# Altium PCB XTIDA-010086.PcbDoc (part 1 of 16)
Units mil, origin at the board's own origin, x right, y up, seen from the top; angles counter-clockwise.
Board outline 14763.78 x 8267.72 mil, 6 copper layers (Top Layer, GND Layer, Signal Layer 1, Signal Layer 2, Power Layer, Bottom Layer), stack 62 mil thick; 1933 components, 1002 nets, 4886 pads, 6482 vias.
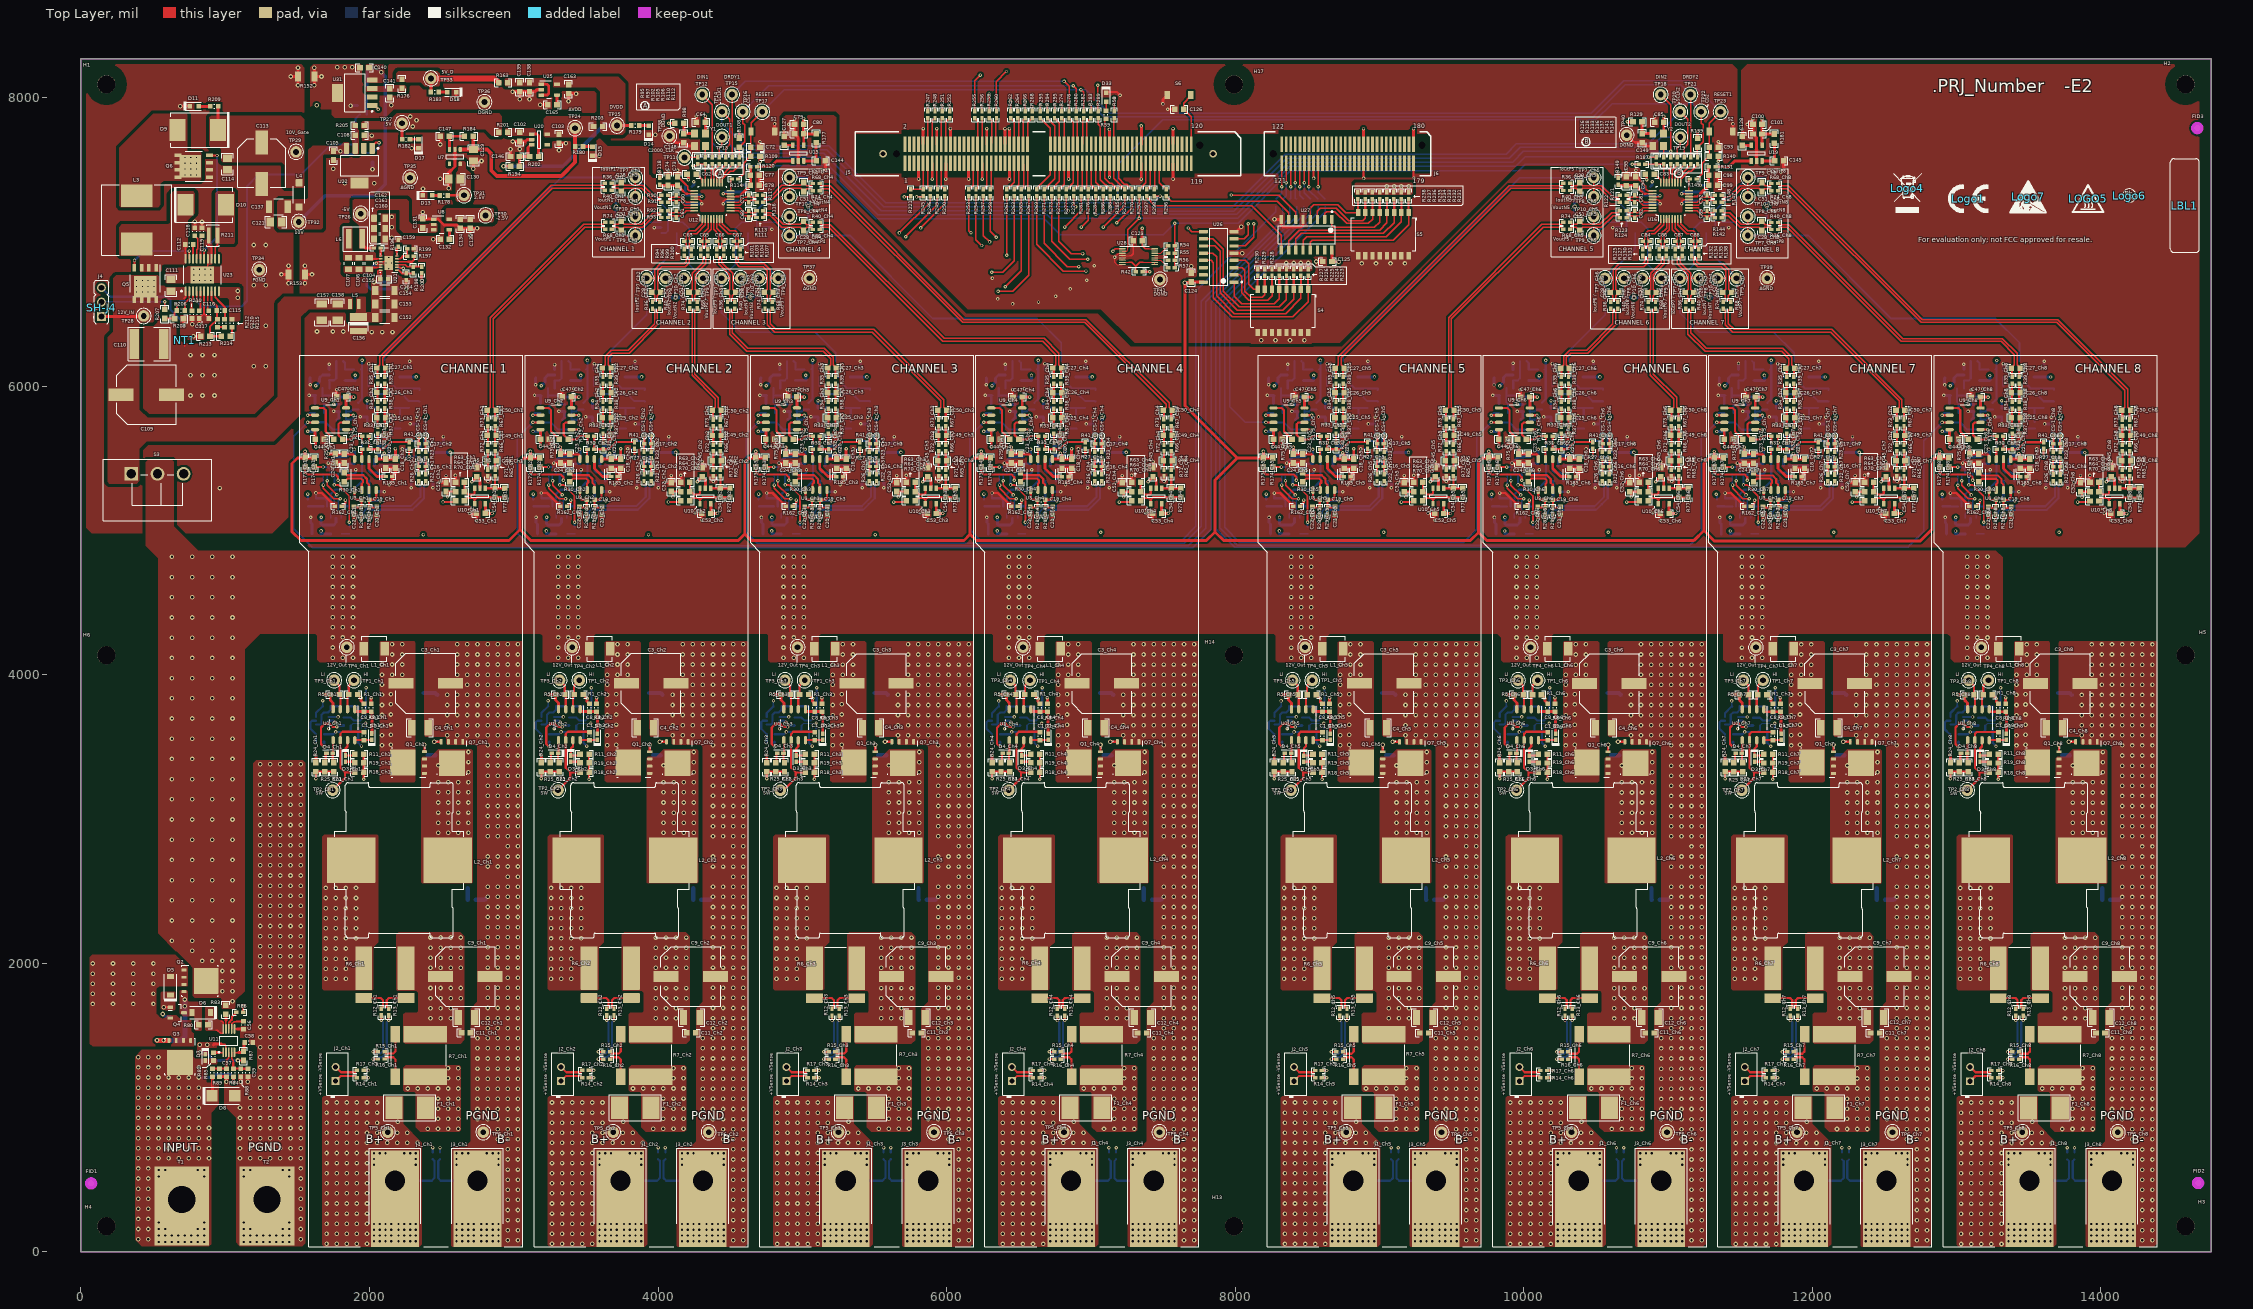
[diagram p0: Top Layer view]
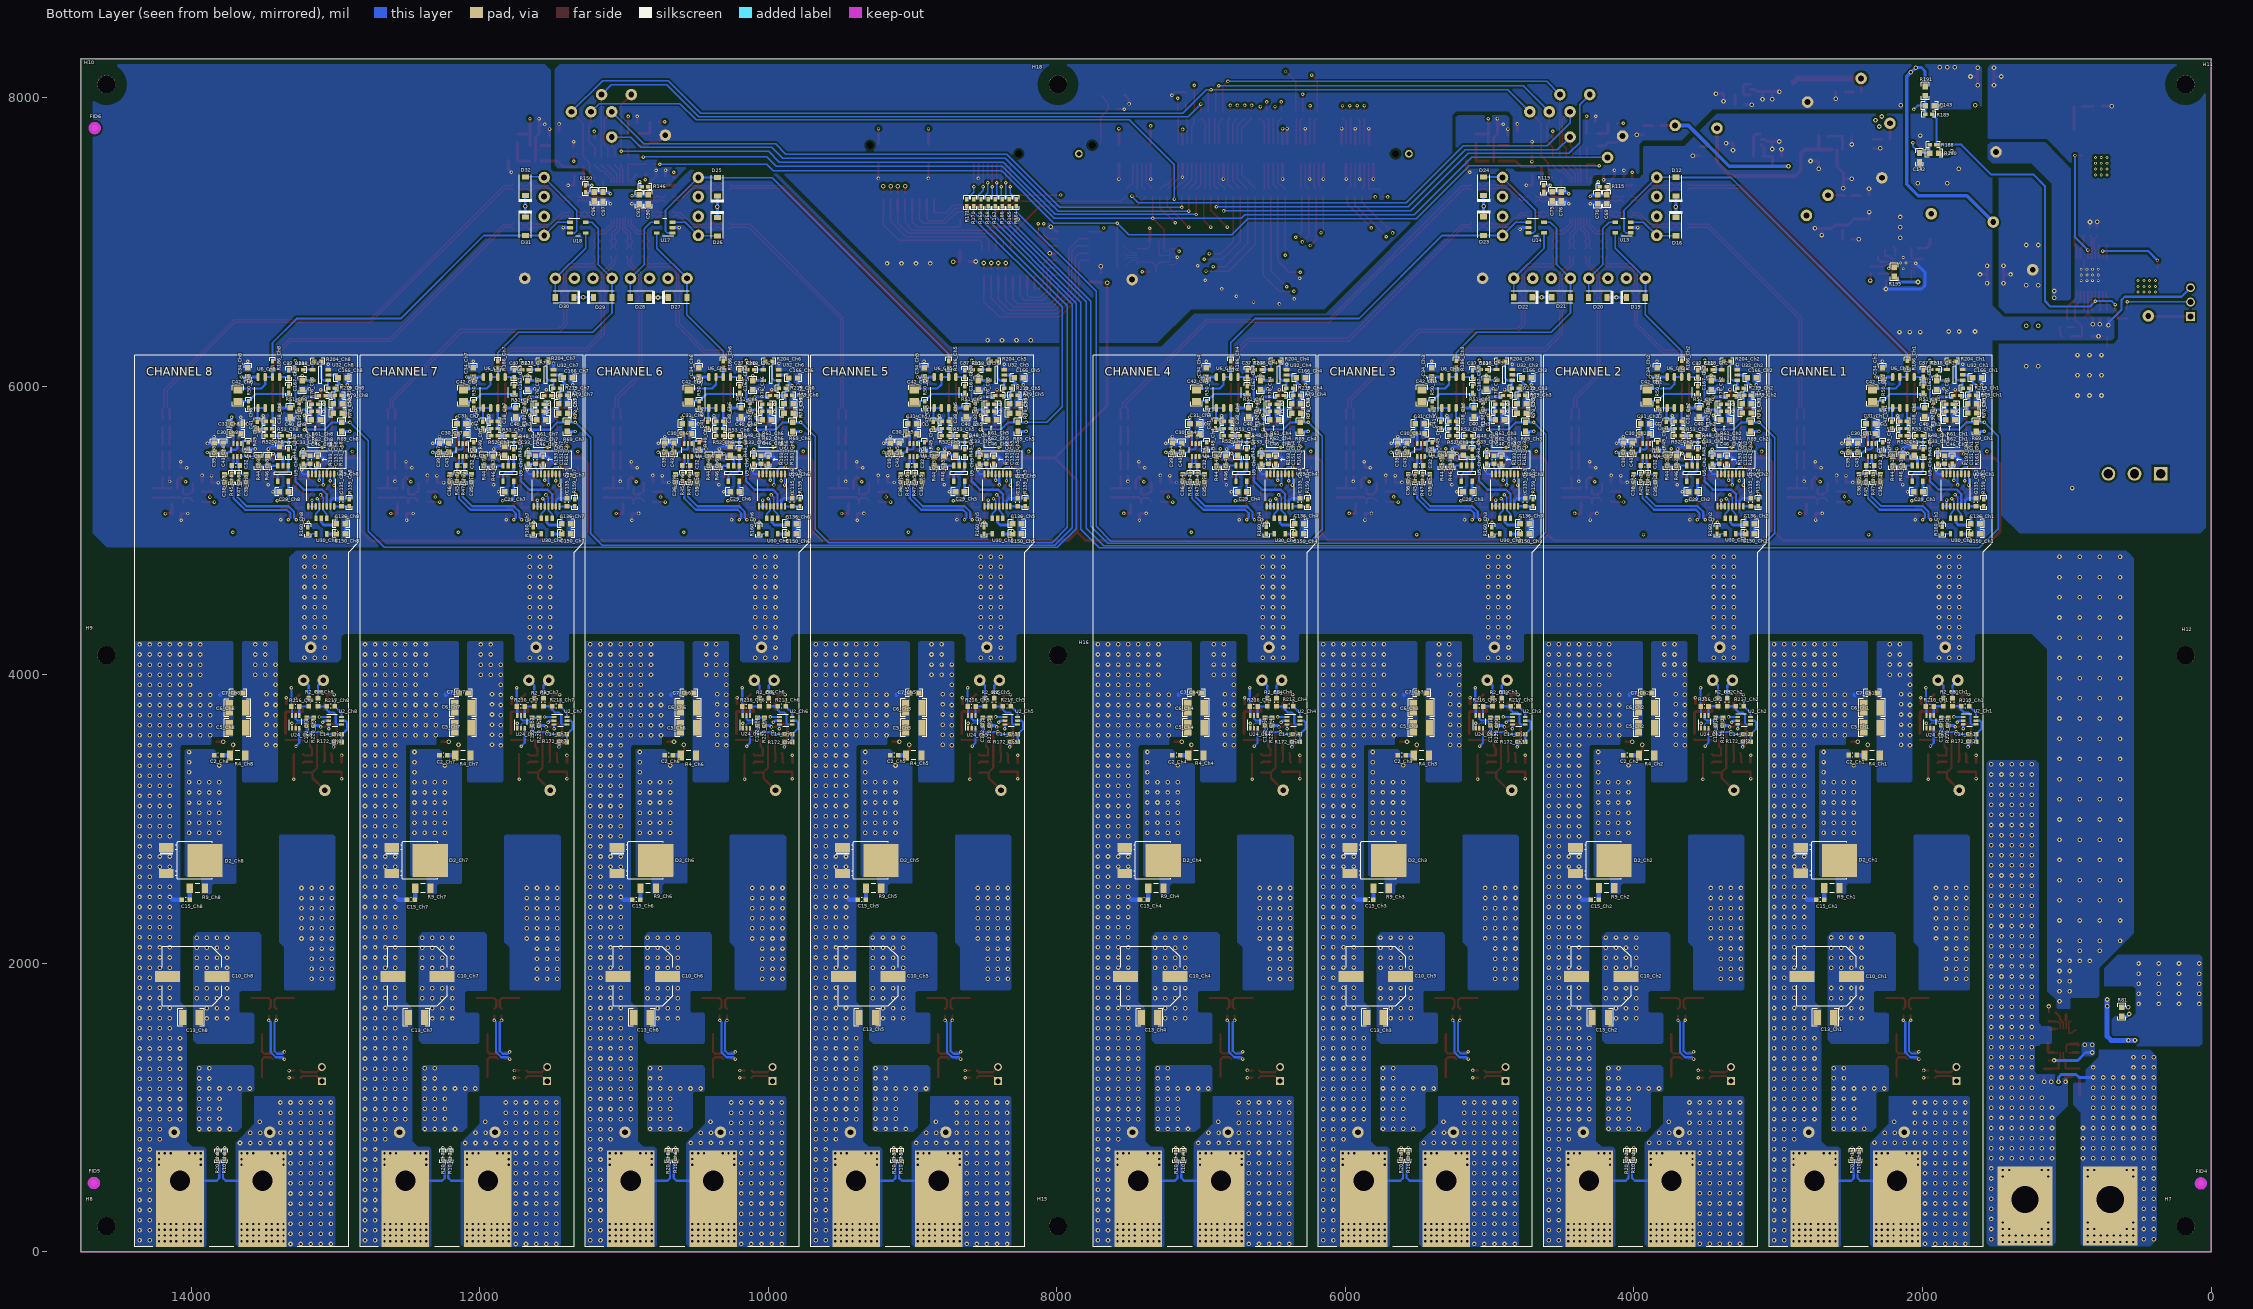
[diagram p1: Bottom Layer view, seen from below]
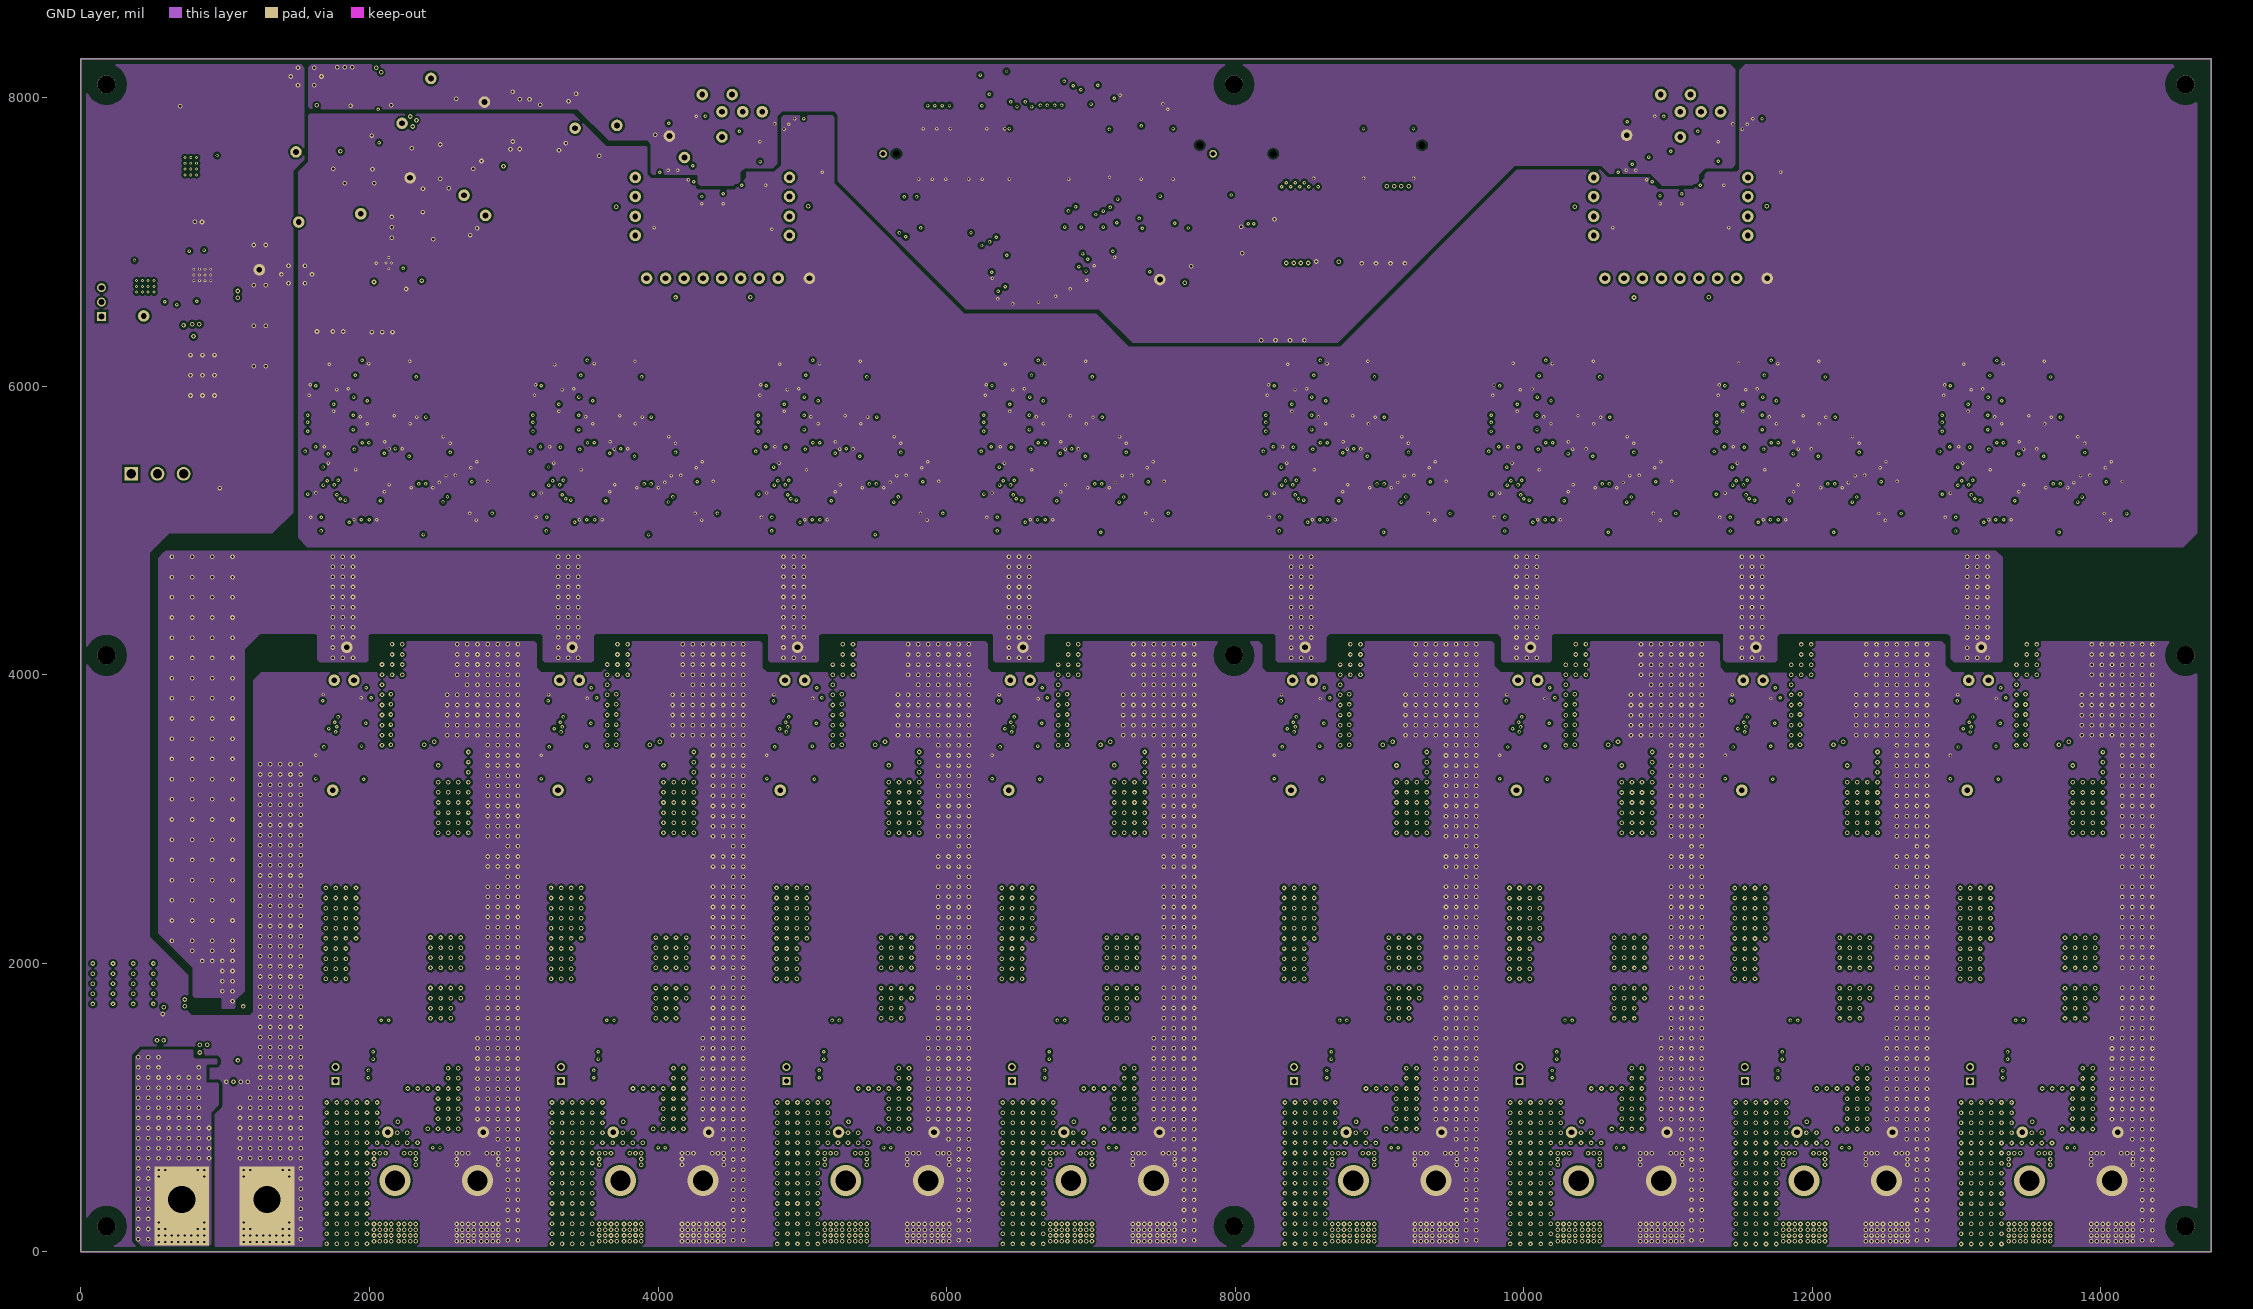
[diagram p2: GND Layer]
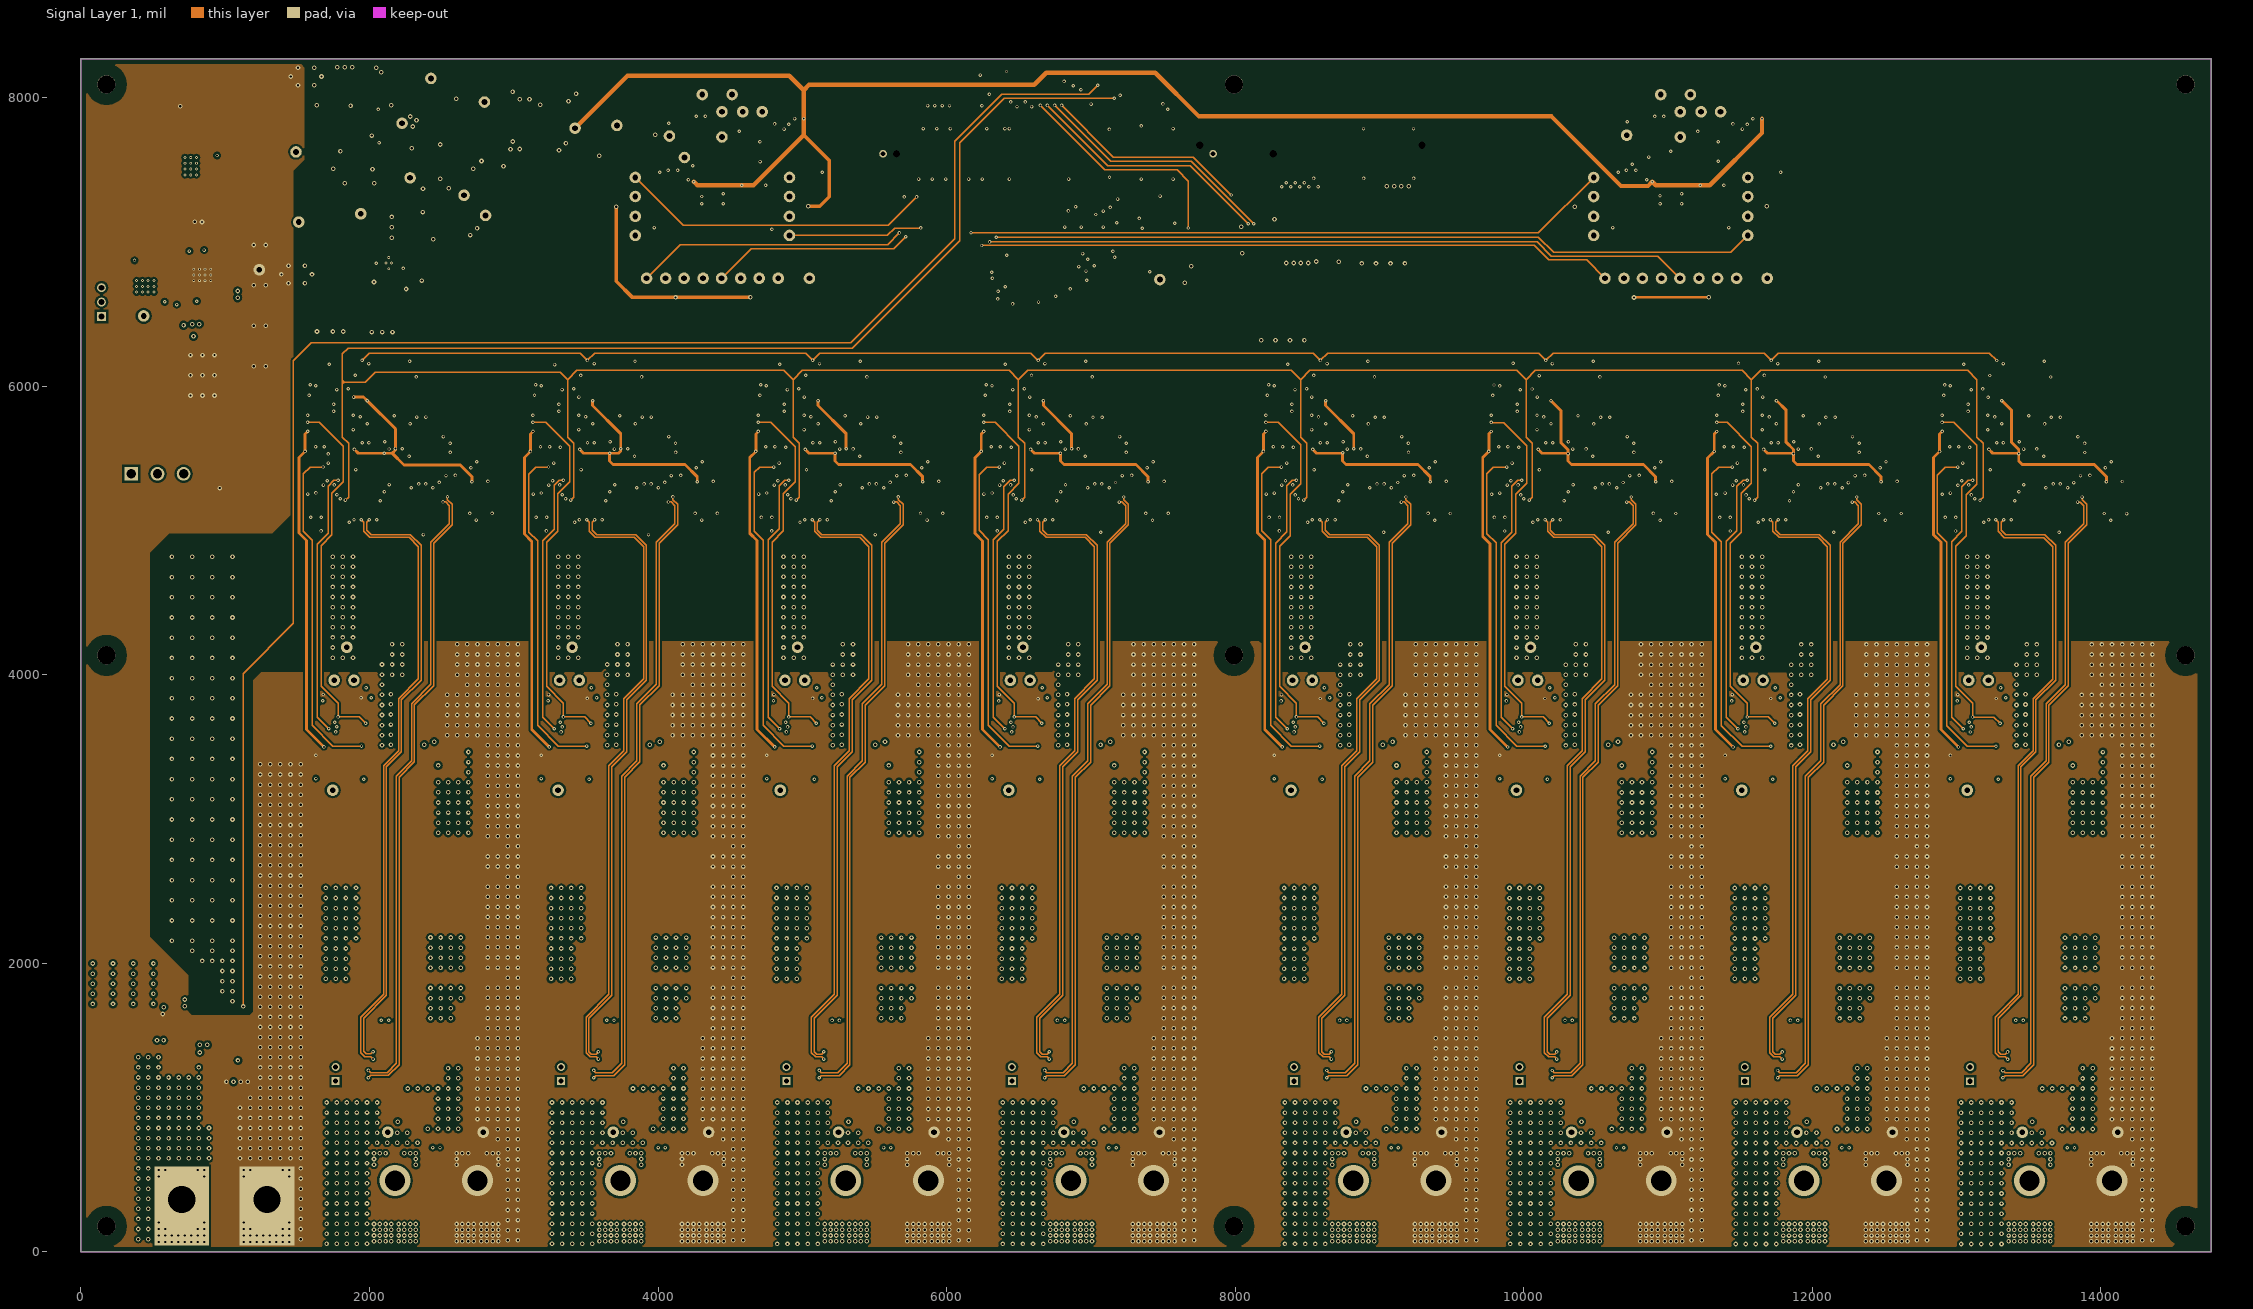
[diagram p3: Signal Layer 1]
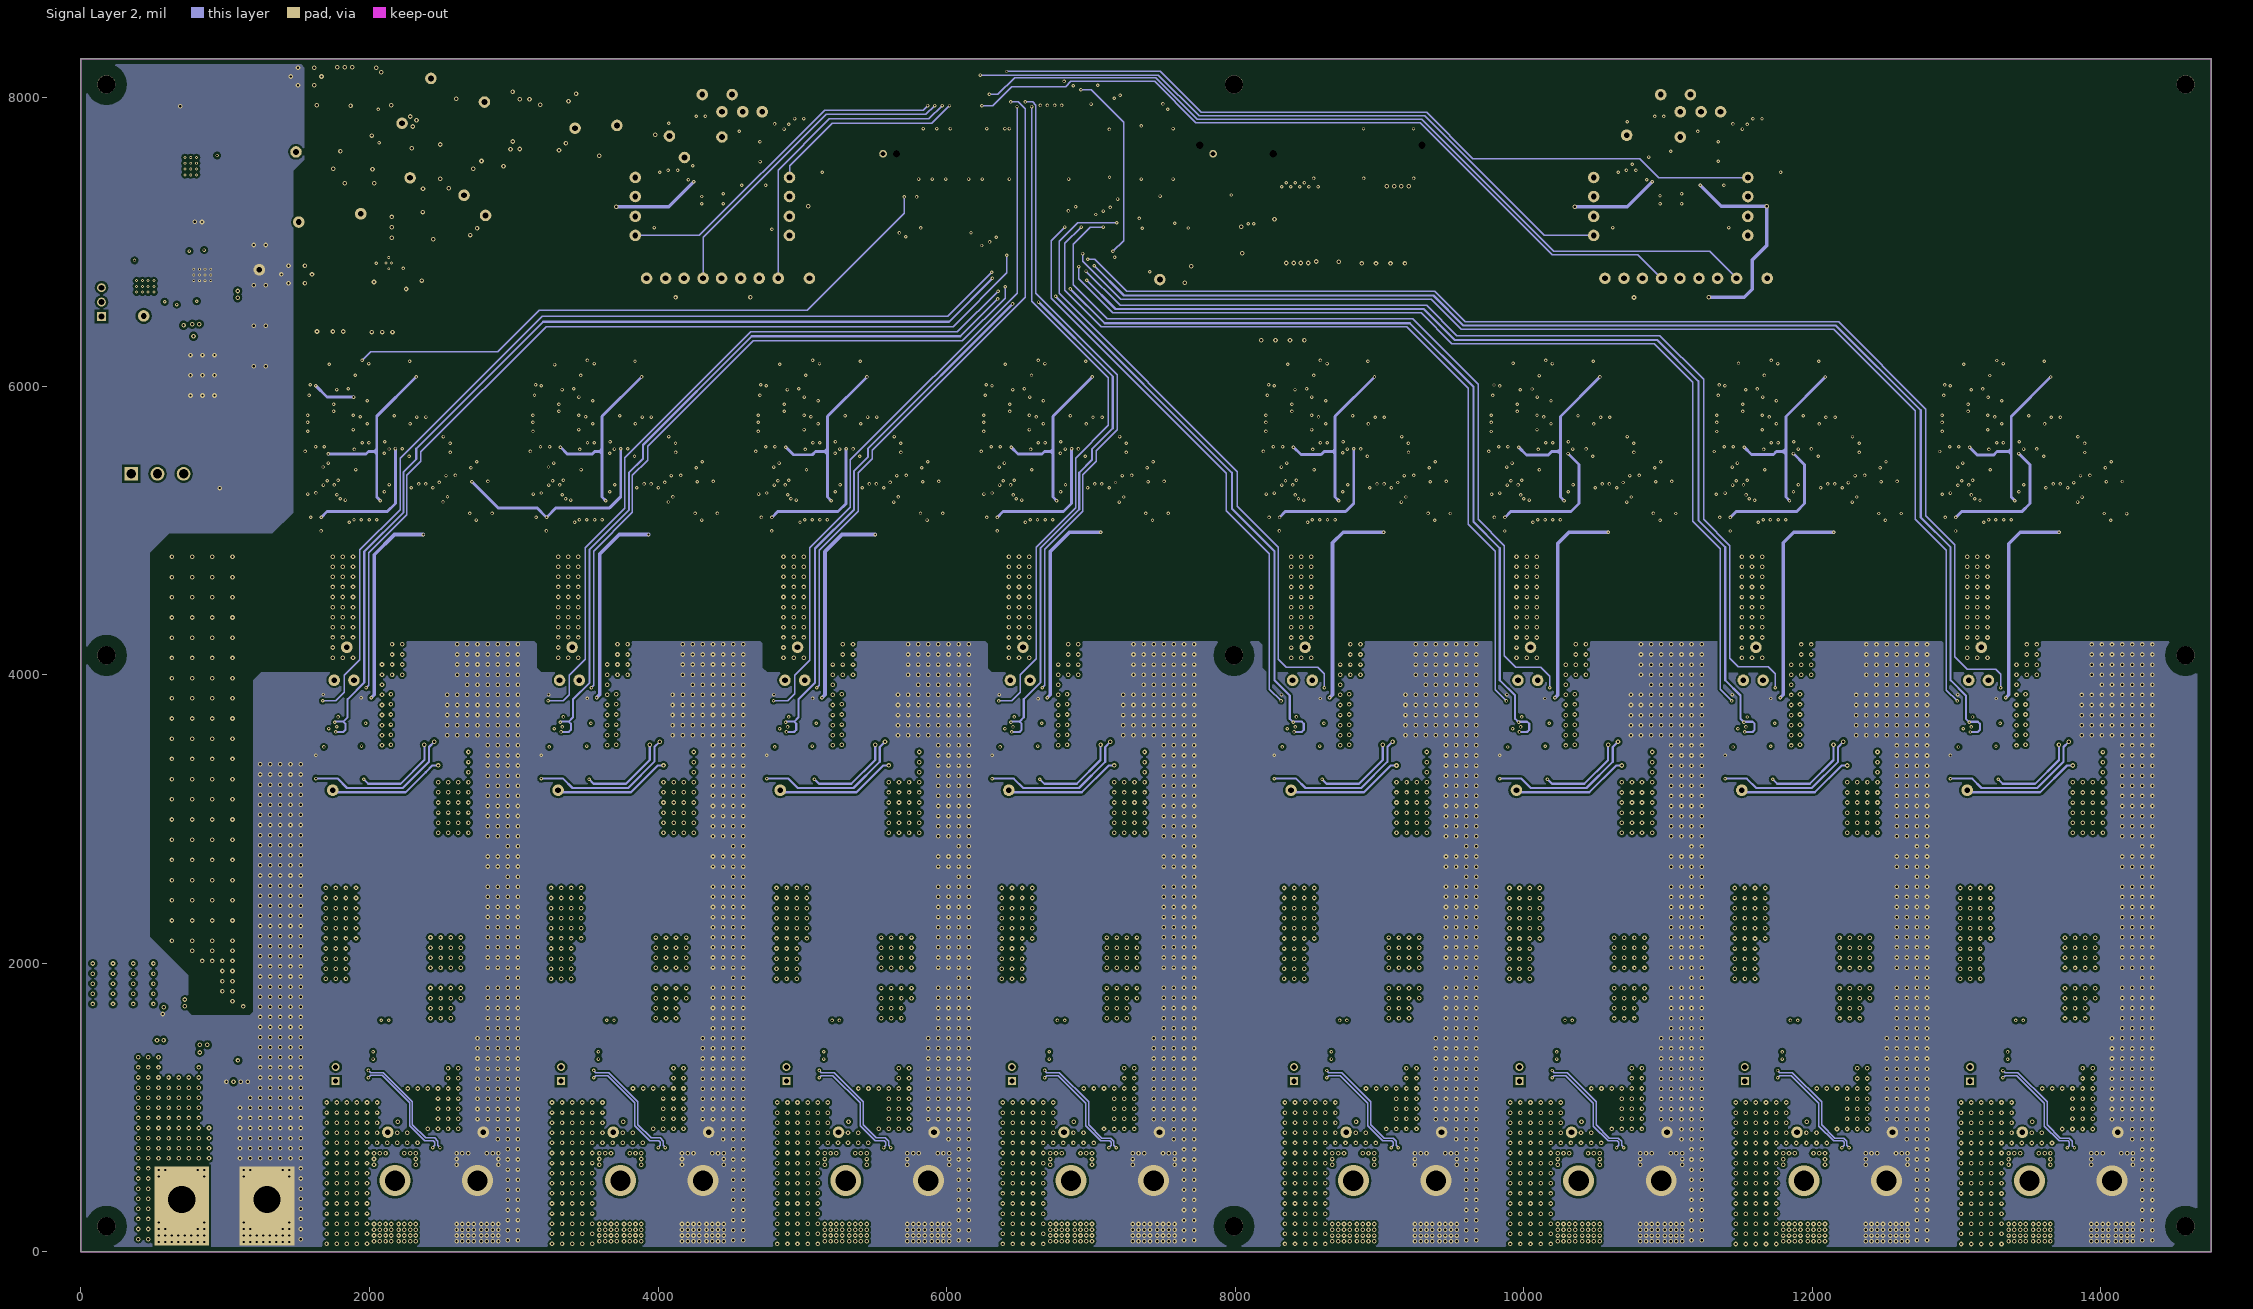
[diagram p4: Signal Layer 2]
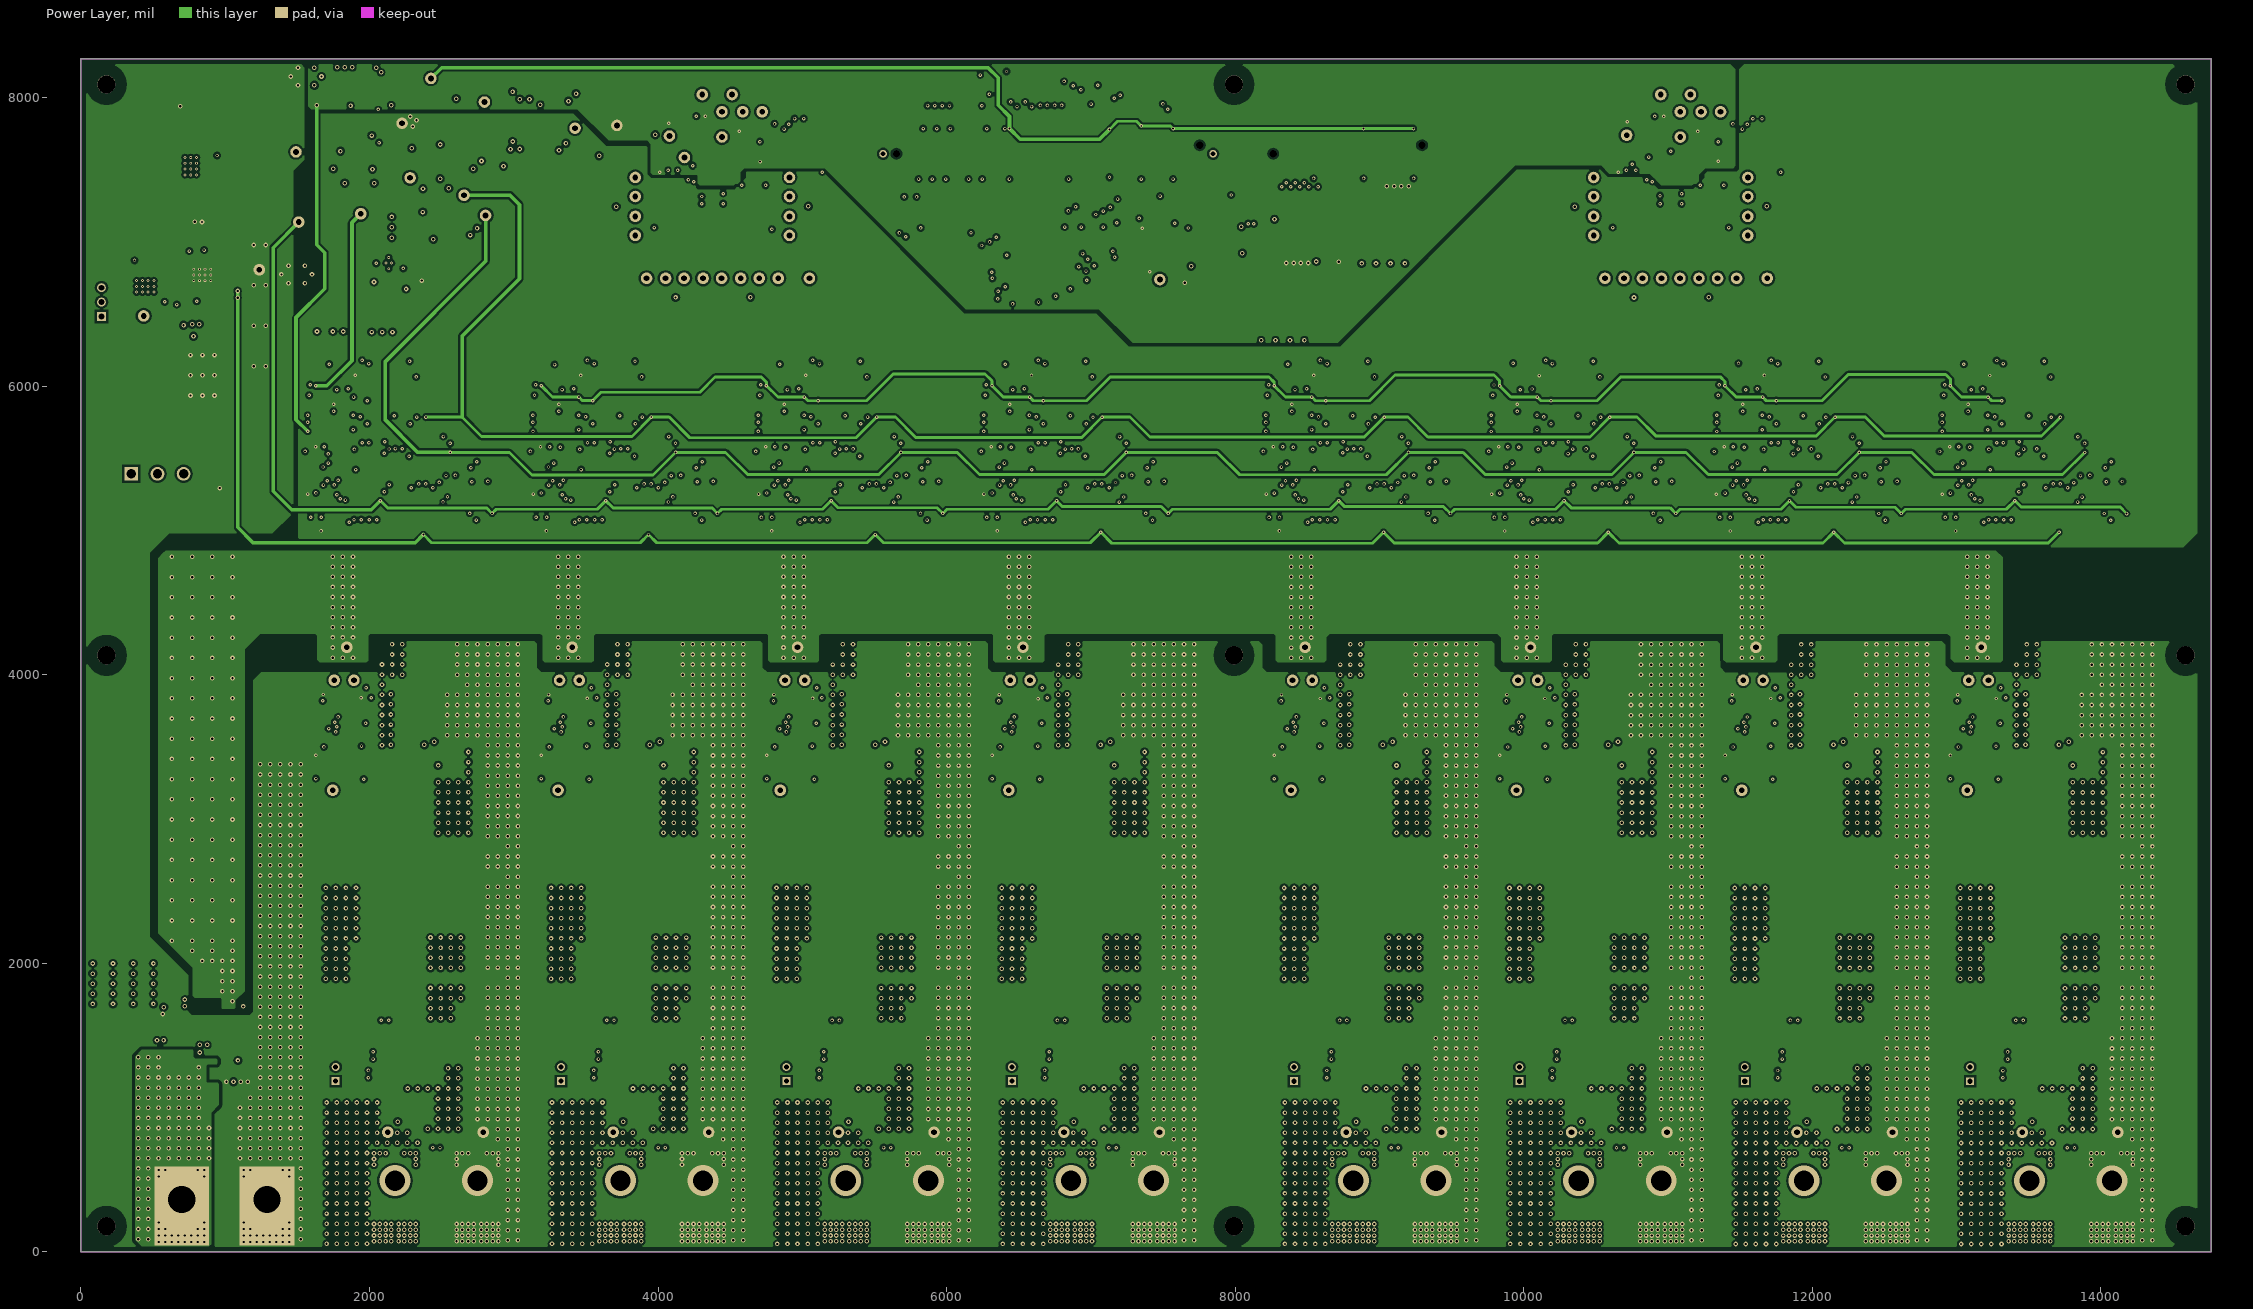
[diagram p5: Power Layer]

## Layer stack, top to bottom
Top Solder: solder mask 0.4, Solder Resist, Dk 3.5
Top Layer: signal copper 2.8
Dielectric 1: dielectric 8, FR-4 High Tg, Dk 4.2
GND Layer: signal copper 2.8
Dielectric2: core 8, FR-4 High Tg, Dk 4.8
Signal Layer 1: signal copper 1.4
Dielectric 3: dielectric 16, FR-4 High Tg, Dk 4.2
Signal Layer 2: signal copper 1.4
Dielectric 4: dielectric 8, FR-4 High Tg, Dk 4.2
Power Layer: signal copper 2.8
Dielectric 5: dielectric 8, FR-4 High Tg, Dk 4.2
Bottom Layer: signal copper 2.8
Bottom Solder: solder mask 0.4, Solder Resist, Dk 3.5

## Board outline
0,0 14763.78,0 14763.78,8267.72 0,8267.72

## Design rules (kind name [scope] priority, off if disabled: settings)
AcuteAngle [All] p1: minimum=4.50000000000000E+0001 checktracksonly=FALSE
AssemblyTestPointUsage [All] p1: valid=2
BoardOutlineClearance [All] p1: gap=25 ignorepadtopadclearanceinfootprint=FALSE
Clearance mounting_hole_clearence [InPadClass('mounting hole') vs InPolygon] p1: gap=80 ignorepadtopadclearanceinfootprint=FALSE
Clearance Clearance_Poly [InPolygon vs InPolygon] p2: gap=25 ignorepadtopadclearanceinfootprint=FALSE
Clearance "Clearance_poly to all" [inpoly] p3: gap=15 ignorepadtopadclearanceinfootprint=FALSE
Clearance [All] p4: gap=6 ignorepadtopadclearanceinfootprint=FALSE except(0: Arc-Arc Arc-SMDPad)
ComponentClearance ComponentClearance_MountingHoles_FiducialMarks [InComponentClass('Mounting Holes') vs InComponentClass('FiducialMark')] p1: gap=10 collisioncheckmode=3 verticalgap=10 showdistances=FALSE
ComponentClearance ComponentClearance_Shunt [InComponentClass('Header') vs InComponentClass('Shunt')] p2: gap=0 collisioncheckmode=3 verticalgap=0 showdistances=FALSE
ComponentClearance ComponentClearance_Logo [InComponentClass('Logo')] p3: gap=10 collisioncheckmode=3 verticalgap=10 showdistances=FALSE
ComponentClearance ComponentClearance_ScrewToNut [(HasFootprint('NY PMS 440 0025 PH')) vs (HasFootprint('Keystone_1902C'))] p4: gap=5 collisioncheckmode=3 verticalgap=10 showdistances=FALSE
ComponentClearance ComponentClearance_MountingHoles [InComponentClass('Mounting Holes')] p5: gap=1 collisioncheckmode=3 verticalgap=100000 showdistances=FALSE
ComponentClearance ComponentClearance_SmallPassives [HasFootprint('0201*') or HasFootprint('0402*') or HasFootprint('0508') or HasFootprint('0603*') or HasFootprint('0612') or HasFootprint('0805*') or HasFootprint('0815*') or HasFootprint('0830*') or HasFootprint('1206*') or HasFootprint('1210*') or HasFootprint('1808*') or HasFootprint('1812*') or HasFootprint('1825*') or HasFootprint('2010*') or HasFootprint('2220*') or HasFootprint('2225*') or HasFootprint('2512*') or HasFootprint('2728*') or HasFootprint('3518*') vs HasFootprint('0201*') or HasFootprint('0402*') or HasFootprint('0508') or HasFootprint('0603*') or HasFootprint('0612') or HasFootprint('0805*') or HasFootprint('0815*') or HasFootprint('0830*') or HasFootprint('1206*') or HasFootprint('1210*') or HasFootprint('1808*') or HasFootprint('1812*') or HasFootprint('1825*') or HasFootprint('2010*') or HasFootprint('2220*') or HasFootprint('2225*') or HasFootprint('2512*') or HasFootprint('2728*') or HasFootprint('3518*')] p6: gap=3 collisioncheckmode=3 verticalgap=3 showdistances=FALSE
ComponentClearance ComponentClearance_THtoSMT [IsThruComponent vs IsSMTComponent] p7: gap=0 collisioncheckmode=3 verticalgap=0 showdistances=FALSE
ComponentClearance ComponentClearance_THtoTH [IsThruComponent vs IsThruComponent] p8: gap=10 collisioncheckmode=3 verticalgap=10 showdistances=FALSE
ComponentClearance [All] p9: gap=1 collisioncheckmode=3 verticalgap=1 showdistances=FALSE
DiffPairsRouting [All] p1: maxlimit=100 minlimit=10 mostfreqgap=10 toplayer_minwidth=10 toplayer_maxwidth=15 toplayer_prefwidth=10 midlayer1_minwidth=10 midlayer1_maxwidth=15 midlayer1_prefwidth=10 midlayer2_minwidth=10 midlayer2_maxwidth=15 midlayer2_prefwidth=10 midlayer3_minwidth=10 midlayer3_maxwidth=15 midlayer3_prefwidth=10 midlayer4_minwidth=10 midlayer4_maxwidth=15 midlayer4_prefwidth=10 bottomlayer_minwidth=10 bottomlayer_maxwidth=15 bottomlayer_prefwidth=10 maxuncoupledlength=1000
FabricationTestPointUsage TestPointUsage [All] p1: valid=2 allowmultiple=FALSE
FabricationTestpoint Testpoint [All] p1: side=3 testpointundercomponent=TRUE minsize=40 maxsize=100 preferedsize=60 minholesize=0 maxholesize=40 preferedholesize=32 testpointgrid=1 allowsidetop=TRUE allowsidebottom=TRUE usegrid=TRUE gridtolerance=0.01
FanoutControl Fanout_LCC [IsLCC] p1: bgadir=Out bgaviamode=Centered fanoutstyle=Auto fanoutdirection=Alternating viagrid=1 // Fanout_LCC (Default Rule)
FanoutControl Fanout_BGA [IsBGA] p2: bgadir=Out bgaviamode=Centered fanoutstyle=Auto fanoutdirection=Alternating viagrid=1 // Fanout_BGA (Default Rule)
FanoutControl Fanout_Default [All] p4: bgadir=Out bgaviamode=Centered fanoutstyle=Auto fanoutdirection=Alternating viagrid=1 // Fanout_Default (Default Rule)
FanoutControl Fanout_Small [(CompPinCount < 5)] p5: bgadir=Out bgaviamode=Centered fanoutstyle=Auto fanoutdirection=OutThenIn viagrid=1 // Fanout_Small (Default Rule)
HoleSize [All] p1: absolutevalues=TRUE maxlimit=251 minlimit=7.87 maxpercent=80.000 minpercent=20.000
MinimumAnnularRing MinimumAnnularRing_ThermalPadVias [IsVia and InAnyComponent] p1: minimumring=5.91
MinimumAnnularRing [All] p2: minimumring=6
MinimumSolderMaskSliver MinimumSolderMaskSliver_Logo [InComponentClass('Logo') vs InComponentClass('Logo')] p1: minsoldermaskwidth=0.7
MinimumSolderMaskSliver [All] p2: minsoldermaskwidth=3.94
PlaneConnect [All] p1: planeconnectstyle=Direct reliefexpansion=10 reliefentries=4 reliefconductorwidth=10 reliefairgap=10
PolygonConnect [All] p1: connectstyle=Direct reliefconductorwidth=10 reliefentries=4 polygonreliefangle="90 Angle" airgapwidth=10
RoomDefinition Hardware [InComponentClass('Hardware')] p1: confinementstyle=ConfineIn formatcopy=TRUE lockcomponents=FALSE outline -1666.26,-1884.85 333.74,-1884.85 333.74,-884.85 -1666.26,-884.85
RoomDefinition "Control Card_28379" [InComponentClass('Control Card_28379')] p2: confinementstyle=ConfineIn formatcopy=TRUE lockcomponents=FALSE outline 5211.39,6377 11079,6377 11079,7785 5211.39,7785
RoomDefinition "Bias Power Supply" [InComponentClass('Bias Power Supply')] p3: confinementstyle=ConfineIn formatcopy=TRUE lockcomponents=FALSE outline 2934.53,5606.32 2934.53,7974.32 73.53,7974.32 73.53,5606.32
RoomDefinition "MAIN SHEET" [InComponentClass('MAIN SHEET')] p4: confinementstyle=ConfineIn formatcopy=TRUE lockcomponents=FALSE outline 1520,-707.44 1520,2159.56 281,2159.56 281,-707.44
RoomDefinition Ch8 [InComponentClass('Ch8')] p5: confinementstyle=ConfineIn formatcopy=TRUE lockcomponents=FALSE outline 14390.7,-432.55 12857.7,-432.55 12857.7,6168 14390.7,6168
RoomDefinition Ch7 [InComponentClass('Ch7')] p6: confinementstyle=ConfineIn formatcopy=TRUE lockcomponents=FALSE outline 12828.7,-432.47 11295.7,-432.47 11295.7,6175 12828.7,6175
RoomDefinition Ch6 [InComponentClass('Ch6')] p7: confinementstyle=ConfineIn formatcopy=TRUE lockcomponents=FALSE outline 11266.7,-432.39 9733.7,-432.39 9733.7,6174 11266.7,6174
RoomDefinition Ch5 [InComponentClass('Ch5')] p8: confinementstyle=ConfineIn formatcopy=TRUE lockcomponents=FALSE outline 9704.7,-432.31 8171.7,-432.31 8171.7,6173 9704.7,6173
RoomDefinition Ch4 [InComponentClass('Ch4')] p9: confinementstyle=ConfineIn formatcopy=TRUE lockcomponents=FALSE outline 7749,-432.24 6216,-432.24 6216,6172 7749,6172
RoomDefinition Ch3 [InComponentClass('Ch3')] p10: confinementstyle=ConfineIn formatcopy=TRUE lockcomponents=FALSE outline 6187,-432.16 4654,-432.16 4654,6170 6187,6170
RoomDefinition Ch2 [InComponentClass('Ch2')] p11: confinementstyle=ConfineIn formatcopy=TRUE lockcomponents=FALSE outline 4625,-432.08 3092,-432.08 3092,6174 4625,6174
RoomDefinition Ch1 [InComponentClass('Ch1')] p12: confinementstyle=ConfineIn formatcopy=TRUE lockcomponents=FALSE outline 3087,-432 1554,-432 1554,6173 3087,6173
RoomDefinition ADC [InComponentClass('ADC')] p13: confinementstyle=ConfineIn formatcopy=TRUE lockcomponents=FALSE outline 2996.42,6382.73 13743.42,6382.73 13743.42,8068.73 2996.42,8068.73
RoutingVias ThermalPadVias [IsVia and InAnyComponent] p1: holewidth=7.87 width=19.68 viastyle="Through Hole" minholewidth=7.87 minwidth=19.68 maxholewidth=12.99 maxwidth=23.62
RoutingVias [All] p2: holewidth=16 width=32 viastyle="Through Hole" minholewidth=12 minwidth=24 maxholewidth=16 maxwidth=32
SilkToBoardRegionClearance [Not ((IsComment or IsDesignator) And (Hide <> 'False')) and not InRegion(1000,500,4000,800)] p1:
SilkToSilkClearance SilkToSilkClearance_Pb-FreeLogo [(HasFootprint('Pb-Free_Overlay_Medium') OR HasFootprint('Pb-Free_Overlay_Small')) vs (HasFootprint('Pb-Free_Overlay_Medium') OR HasFootprint('Pb-Free_Overlay_Small'))] p1: silktosilkclearance=0
SilkToSilkClearance [All] p2: silktosilkclearance=2
SilkToSolderMaskClearance SilkToComponentPadClearance [(IsPad or IsFill or IsRegion) and InAnycomponent] p1: minsilkscreentomaskgap=5 clearancetoexposedcopper=TRUE
SilkToSolderMaskClearance "Silk to Solder Mask Opening" [All] p2: minsilkscreentomaskgap=4 clearancetoexposedcopper=FALSE
SolderMaskExpansion [All] p1: expansion=1.97
Width [All] p1: maxlimit=100 minlimit=6 preferedwidth=10 checkconnectedcopper=TRUE
15 further rules are at their usual default settings.

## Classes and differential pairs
net class Interrupt[1..8]: Interrupt1 Interrupt2 Interrupt3 Interrupt4 Interrupt5 Interrupt6 Interrupt7 Interrupt8
channel class "XTIDA-010086_Power Stage": Ch1 Ch2 Ch3 Ch4 Ch5 Ch6 Ch7 Ch8
component class "Control Card_28379": C124 C125 C126 D33 J5 J6 R58 R59 R164 R165 R166 R167 R168 R169 R170 R171 R221 R223 R224 R225 R226 R227 R228 R229 R230 R231 R232 R233 R234 R235 R236 R237 R238 R245 R246 R247 R248 R249 R250 R251 R252 R253 R254 R255 R256 R257 R258 R259 R260 R261 R262 R263 R264 R265 R266 R267 R268 R269 R270 R271 R272 R273 R274 R275 R276 R277 R278 R279 R280 R281 R282 R283 R284 R285 R286 R288 R289 R292 R293 R294 R295 R296 R297 R298 S4 S5 S6 TP41 U26 U27
differential pair class 100Ohm: ADC_Iout1 ADC_Iout2 ADC_Iout3 ADC_Iout4 ADC_Iout5 ADC_Iout6 ADC_Iout7 ADC_Iout8 ADC_Vout1 ADC_Vout2 ADC_Vout3 ADC_Vout4 ADC_Vout5 ADC_Vout6 ADC_Vout7 ADC_Vout8 Ch1_Iout1 Ch1_Vout1 Ch2_Iout2 Ch2_Vout2 Ch3_Iout3 Ch3_Vout3 Ch4_Iout4 Ch4_Vout4 Ch5_Iout5 Ch5_Vout5 Ch6_Iout6 Ch6_Vout6 Ch7_Iout7 Ch7_Vout7 Ch8_Iout8 Ch8_Vout8 CS_CH1 CS_CH2 CS_CH3 CS_CH4 CS_CH5 CS_CH6 CS_CH7 CS_CH8 Iout1 Iout2 Iout3 Iout4 Iout5 Iout6 Iout7 Iout8 R_CS_CH1 Vout1 Vout2 Vout3 Vout4 Vout5 Vout6 Vout7 Vout8 VSense_CH1 VSense_CH2 VSense_CH3 VSense_CH4 VSense_CH5 VSense_CH6 VSense_CH7 VSense_CH8
component class ADC: C60 C61 C62 C63 C64 C65 C66 C67 C68 C69 C70 C71 C72 C73 C74 C75 C76 C77 C78 C79 C80 C81 C82 C83 C84 C85 C86 C87 C88 C89 C90 C91 C92 C93 C94 C95 C96 C97 C98 C99 C100 C101 C123 C127 C128 C144 C145 C148 C149 D12 D16 D19 D20 D21 D22 D23 D24 D25 D26 D27 D28 D29 D30 D31 D32 R42 R54 R55 R56 R57 R90 R91 R92 R93 R94 R95 R96 R97 R98 R99 R100 R101 R102 R103 R104 R105 R106 R107 R108 R109 R110 R111 R112 R113 R114 R115 R116 R117 R118 R119 R120 R121 R122 R123 R124 R125 R126 R127 R128 R129 R130 R131 R132 R133 R134 R135 R136 R137 R138 R139 R140 R141 R142 R143 R144 R145 R146 R147 R148 R149 R150 R151 R152 R153 R177 R181 R187 S1 S2 TP11 TP12 TP13 TP14 TP15 TP16 TP17 TP18 TP19 TP20 TP21 TP22 TP23 TP37 TP38 TP39 TP40 U12 U13 U14 U15 U16 U17 U18 U19 U28 Y1 Y2
net class VoutP[1..8]: VoutP1 VoutP2 VoutP3 VoutP4 VoutP5 VoutP6 VoutP7 VoutP8
net class VoutN[1..8]: VoutN1 VoutN2 VoutN3 VoutN4 VoutN5 VoutN6 VoutN7 VoutN8
net class IoutP[1..8]: IoutP1 IoutP2 IoutP3 IoutP4 IoutP5 IoutP6 IoutP7 IoutP8
net class IoutN[1..8]: IoutN1 IoutN2 IoutN3 IoutN4 IoutN5 IoutN6 IoutN7 IoutN8
net class EPWM_B[1..8]: EPWM_B1 EPWM_B2 EPWM_B3 EPWM_B4 EPWM_B5 EPWM_B6 EPWM_B7 EPWM_B8
net class EPWM_A[1..8]: EPWM_A1 EPWM_A2 EPWM_A3 EPWM_A4 EPWM_A5 EPWM_A6 EPWM_A7 EPWM_A8
component class "MAIN SHEET": C56 C57 C58 C59 D5 D6 D7 D8 Q2 Q3 Q4 R80 R81 R82 R83 R84 R85 R86 R87 R88 R89 T1 T2 U11
component class Ch8: C1_Ch8 C2_Ch8 C3_Ch8 C4_Ch8 C5_Ch8 C6_Ch8 C7_Ch8 C8_Ch8 C9_Ch8 C10_Ch8 C11_Ch8 C12_Ch8 C13_Ch8 C14_Ch8 C15_Ch8 C16_Ch8 C17_Ch8 C18_Ch8 C19_Ch8 C20_Ch8 C21_Ch8 C22_Ch8 C23_Ch8 C24_Ch8 C25_Ch8 C26_Ch8 C27_Ch8 C28_Ch8 C29_Ch8 C30_Ch8 C31_Ch8 C32_Ch8 C33_Ch8 C34_Ch8 C35_Ch8 C36_Ch8 C37_Ch8 C38_Ch8 C39_Ch8 C40_Ch8 C41_Ch8 C42_Ch8 C43_Ch8 C44_Ch8 C45_Ch8 C46_Ch8 C47_Ch8 C48_Ch8 C49_Ch8 C50_Ch8 C51_Ch8 C52_Ch8 C53_Ch8 C54_Ch8 C55_Ch8 C56_Ch8 C57_Ch8 C58_Ch8 C59_Ch8 C60_Ch8 C61_Ch8 C62_Ch8 C63_Ch8 C64_Ch8 C65_Ch8 C66_Ch8 C67_Ch8 C68_Ch8 C69_Ch8 C70_Ch8 C71_Ch8 C72_Ch8 C73_Ch8 C74_Ch8 C75_Ch8 C76_Ch8 C77_Ch8 C78_Ch8 C79_Ch8 C80_Ch8 C81_Ch8 C82_Ch8 C83_Ch8 C84_Ch8 C85_Ch8 C86_Ch8 C87_Ch8 C88_Ch8 C89_Ch8 C90_Ch8 C91_Ch8 C92_Ch8 C93_Ch8 C94_Ch8 C95_Ch8 C96_Ch8 C97_Ch8 C98_Ch8 C99_Ch8 C100_Ch8 C101_Ch8 C102_Ch8 C103_Ch8 C122_Ch8 C135_Ch8 C136_Ch8 C150_Ch8 C151_Ch8 C166_Ch8 C167_Ch8 CS+1_Ch8 CS-1_Ch8 D1_Ch8 D2_Ch8 D3_Ch8 D4_Ch8 D5_Ch8 D6_Ch8 D7_Ch8 D10_Ch8 F1_Ch8 J1_Ch8 J2_Ch8 J3_Ch8 L1_Ch8 L2_Ch8 Q1_Ch8 Q7_Ch8 R1_Ch8 R2_Ch8 R3_Ch8 R4_Ch8 R5_Ch8 R6_Ch8 R7_Ch8 R8_Ch8 R9_Ch8 R10_Ch8 R11_Ch8 R12_Ch8 R13_Ch8 R14_Ch8 R15_Ch8 R16_Ch8 R17_Ch8 R18_Ch8 R19_Ch8 R20_Ch8 R21_Ch8 R22_Ch8 R23_Ch8 R24_Ch8 R25_Ch8 R26_Ch8 R27_Ch8 R28_Ch8 R29_Ch8 R30_Ch8 R31_Ch8 R32_Ch8 R33_Ch8 R34_Ch8 R35_Ch8 R36_Ch8 R37_Ch8 R38_Ch8 R39_Ch8 R40_Ch8 R41_Ch8 R43_Ch8 R44_Ch8 R45_Ch8 R46_Ch8 R47_Ch8 R48_Ch8 R49_Ch8 R50_Ch8 R51_Ch8 R52_Ch8 R53_Ch8 R61_Ch8 R62_Ch8 R63_Ch8 R64_Ch8 R65_Ch8 R66_Ch8 R67_Ch8 R68_Ch8 R69_Ch8 R70_Ch8 R71_Ch8 R72_Ch8 R73_Ch8 R74_Ch8 R75_Ch8 R76_Ch8 R77_Ch8 R78_Ch8 R79_Ch8 R93_Ch8 R95_Ch8 R96_Ch8 R97_Ch8 R98_Ch8 R99_Ch8 R100_Ch8 R101_Ch8 R102_Ch8 R103_Ch8 R104_Ch8 R105_Ch8 R107_Ch8 R110_Ch8 R111_Ch8 R113_Ch8 R114_Ch8 R115_Ch8 R116_Ch8 R117_Ch8 R118_Ch8 R119_Ch8 R120_Ch8 R121_Ch8 R122_Ch8 R123_Ch8 R124_Ch8 R125_Ch8 R126_Ch8 R127_Ch8 R128_Ch8 R129_Ch8 R130_Ch8 R131_Ch8 R132_Ch8 R133_Ch8 R134_Ch8 R138_Ch8 R139_Ch8 R140_Ch8 R141_Ch8 R142_Ch8 R143_Ch8 R144_Ch8 R145_Ch8 R146_Ch8 R147_Ch8 R148_Ch8 R149_Ch8 R150_Ch8 R151_Ch8 R152_Ch8 R153_Ch8 R154_Ch8 R155_Ch8 R158_Ch8 R159_Ch8 R160_Ch8 R161_Ch8 R162_Ch8 R164_Ch8 R165_Ch8 R166_Ch8 R167_Ch8 R168_Ch8 R169_Ch8 R170_Ch8 R171_Ch8 R172_Ch8 R173_Ch8 R174_Ch8 R175_Ch8 R176_Ch8 R185_Ch8 R186_Ch8 R192_Ch8 R193_Ch8 R204_Ch8 R216_Ch8 R217_Ch8 R218_Ch8 R219_Ch8 R220_Ch8 TP1_Ch8 TP2_Ch8 TP3_Ch8 TP4_Ch8 TP5_Ch8 TP6_Ch8 TP7_Ch8 TP8_Ch8 TP9_Ch8 TP10_Ch8 U1_Ch8 U2_Ch8 U3_Ch8 U4_Ch8 U5_Ch8 U6_Ch8 U9_Ch8 U10_Ch8 U17_Ch8 U18_Ch8 U19_Ch8 U20_Ch8 U21_Ch8 U22_Ch8 U24_Ch8 U29_Ch8 U30_Ch8 U32_Ch8
component class Ch7: C1_Ch7 C2_Ch7 C3_Ch7 C4_Ch7 C5_Ch7 C6_Ch7 C7_Ch7 C8_Ch7 C9_Ch7 C10_Ch7 C11_Ch7 C12_Ch7 C13_Ch7 C14_Ch7 C15_Ch7 C16_Ch7 C17_Ch7 C18_Ch7 C19_Ch7 C20_Ch7 C21_Ch7 C22_Ch7 C23_Ch7 C24_Ch7 C25_Ch7 C26_Ch7 C27_Ch7 C28_Ch7 C29_Ch7 C30_Ch7 C31_Ch7 C32_Ch7 C33_Ch7 C34_Ch7 C35_Ch7 C36_Ch7 C37_Ch7 C38_Ch7 C39_Ch7 C40_Ch7 C41_Ch7 C42_Ch7 C43_Ch7 C44_Ch7 C45_Ch7 C46_Ch7 C47_Ch7 C48_Ch7 C49_Ch7 C50_Ch7 C51_Ch7 C52_Ch7 C53_Ch7 C54_Ch7 C55_Ch7 C56_Ch7 C57_Ch7 C58_Ch7 C59_Ch7 C60_Ch7 C61_Ch7 C62_Ch7 C63_Ch7 C64_Ch7 C65_Ch7 C66_Ch7 C67_Ch7 C68_Ch7 C69_Ch7 C70_Ch7 C71_Ch7 C72_Ch7 C73_Ch7 C74_Ch7 C75_Ch7 C76_Ch7 C77_Ch7 C78_Ch7 C79_Ch7 C80_Ch7 C81_Ch7 C82_Ch7 C83_Ch7 C84_Ch7 C85_Ch7 C86_Ch7 C87_Ch7 C88_Ch7 C89_Ch7 C90_Ch7 C91_Ch7 C92_Ch7 C93_Ch7 C94_Ch7 C95_Ch7 C96_Ch7 C97_Ch7 C98_Ch7 C99_Ch7 C100_Ch7 C101_Ch7 C102_Ch7 C103_Ch7 C122_Ch7 C135_Ch7 C136_Ch7 C150_Ch7 C151_Ch7 C166_Ch7 C167_Ch7 CS+1_Ch7 CS-1_Ch7 D1_Ch7 D2_Ch7 D3_Ch7 D4_Ch7 D5_Ch7 D6_Ch7 D7_Ch7 D10_Ch7 F1_Ch7 J1_Ch7 J2_Ch7 J3_Ch7 L1_Ch7 L2_Ch7 Q1_Ch7 Q7_Ch7 R1_Ch7 R2_Ch7 R3_Ch7 R4_Ch7 R5_Ch7 R6_Ch7 R7_Ch7 R8_Ch7 R9_Ch7 R10_Ch7 R11_Ch7 R12_Ch7 R13_Ch7 R14_Ch7 R15_Ch7 R16_Ch7 R17_Ch7 R18_Ch7 R19_Ch7 R20_Ch7 R21_Ch7 R22_Ch7 R23_Ch7 R24_Ch7 R25_Ch7 R26_Ch7 R27_Ch7 R28_Ch7 R29_Ch7 R30_Ch7 R31_Ch7 R32_Ch7 R33_Ch7 R34_Ch7 R35_Ch7 R36_Ch7 R37_Ch7 R38_Ch7 R39_Ch7 R40_Ch7 R41_Ch7 R43_Ch7 R44_Ch7 R45_Ch7 R46_Ch7 R47_Ch7 R48_Ch7 R49_Ch7 R50_Ch7 R51_Ch7 R52_Ch7 R53_Ch7 R61_Ch7 R62_Ch7 R63_Ch7 R64_Ch7 R65_Ch7 R66_Ch7 R67_Ch7 R68_Ch7 R69_Ch7 R70_Ch7 R71_Ch7 R72_Ch7 R73_Ch7 R74_Ch7 R75_Ch7 R76_Ch7 R77_Ch7 R78_Ch7 R79_Ch7 R93_Ch7 R95_Ch7 R96_Ch7 R97_Ch7 R98_Ch7 R99_Ch7 R100_Ch7 R101_Ch7 R102_Ch7 R103_Ch7 R104_Ch7 R105_Ch7 R107_Ch7 R110_Ch7 R111_Ch7 R113_Ch7 R114_Ch7 R115_Ch7 R116_Ch7 R117_Ch7 R118_Ch7 R119_Ch7 R120_Ch7 R121_Ch7 R122_Ch7 R123_Ch7 R124_Ch7 R125_Ch7 R126_Ch7 R127_Ch7 R128_Ch7 R129_Ch7 R130_Ch7 R131_Ch7 R132_Ch7 R133_Ch7 R134_Ch7 R138_Ch7 R139_Ch7 R140_Ch7 R141_Ch7 R142_Ch7 R143_Ch7 R144_Ch7 R145_Ch7 R146_Ch7 R147_Ch7 R148_Ch7 R149_Ch7 R150_Ch7 R151_Ch7 R152_Ch7 R153_Ch7 R154_Ch7 R155_Ch7 R158_Ch7 R159_Ch7 R160_Ch7 R161_Ch7 R162_Ch7 R164_Ch7 R165_Ch7 R166_Ch7 R167_Ch7 R168_Ch7 R169_Ch7 R170_Ch7 R171_Ch7 R172_Ch7 R173_Ch7 R174_Ch7 R175_Ch7 R176_Ch7 R185_Ch7 R186_Ch7 R192_Ch7 R193_Ch7 R204_Ch7 R216_Ch7 R217_Ch7 R218_Ch7 R219_Ch7 R220_Ch7 TP1_Ch7 TP2_Ch7 TP3_Ch7 TP4_Ch7 TP5_Ch7 TP6_Ch7 TP7_Ch7 TP8_Ch7 TP9_Ch7 TP10_Ch7 U1_Ch7 U2_Ch7 U3_Ch7 U4_Ch7 U5_Ch7 U6_Ch7 U9_Ch7 U10_Ch7 U17_Ch7 U18_Ch7 U19_Ch7 U20_Ch7 U21_Ch7 U22_Ch7 U24_Ch7 U29_Ch7 U30_Ch7 U32_Ch7
component class Ch6: C1_Ch6 C2_Ch6 C3_Ch6 C4_Ch6 C5_Ch6 C6_Ch6 C7_Ch6 C8_Ch6 C9_Ch6 C10_Ch6 C11_Ch6 C12_Ch6 C13_Ch6 C14_Ch6 C15_Ch6 C16_Ch6 C17_Ch6 C18_Ch6 C19_Ch6 C20_Ch6 C21_Ch6 C22_Ch6 C23_Ch6 C24_Ch6 C25_Ch6 C26_Ch6 C27_Ch6 C28_Ch6 C29_Ch6 C30_Ch6 C31_Ch6 C32_Ch6 C33_Ch6 C34_Ch6 C35_Ch6 C36_Ch6 C37_Ch6 C38_Ch6 C39_Ch6 C40_Ch6 C41_Ch6 C42_Ch6 C43_Ch6 C44_Ch6 C45_Ch6 C46_Ch6 C47_Ch6 C48_Ch6 C49_Ch6 C50_Ch6 C51_Ch6 C52_Ch6 C53_Ch6 C54_Ch6 C55_Ch6 C56_Ch6 C57_Ch6 C58_Ch6 C59_Ch6 C60_Ch6 C61_Ch6 C62_Ch6 C63_Ch6 C64_Ch6 C65_Ch6 C66_Ch6 C67_Ch6 C68_Ch6 C69_Ch6 C70_Ch6 C71_Ch6 C72_Ch6 C73_Ch6 C74_Ch6 C75_Ch6 C76_Ch6 C77_Ch6 C78_Ch6 C79_Ch6 C80_Ch6 C81_Ch6 C82_Ch6 C83_Ch6 C84_Ch6 C85_Ch6 C86_Ch6 C87_Ch6 C88_Ch6 C89_Ch6 C90_Ch6 C91_Ch6 C92_Ch6 C93_Ch6 C94_Ch6 C95_Ch6 C96_Ch6 C97_Ch6 C98_Ch6 C99_Ch6 C100_Ch6 C101_Ch6 C102_Ch6 C103_Ch6 C122_Ch6 C135_Ch6 C136_Ch6 C150_Ch6 C151_Ch6 C166_Ch6 C167_Ch6 CS+1_Ch6 CS-1_Ch6 D1_Ch6 D2_Ch6 D3_Ch6 D4_Ch6 D5_Ch6 D6_Ch6 D7_Ch6 D10_Ch6 F1_Ch6 J1_Ch6 J2_Ch6 J3_Ch6 L1_Ch6 L2_Ch6 Q1_Ch6 Q7_Ch6 R1_Ch6 R2_Ch6 R3_Ch6 R4_Ch6 R5_Ch6 R6_Ch6 R7_Ch6 R8_Ch6 R9_Ch6 R10_Ch6 R11_Ch6 R12_Ch6 R13_Ch6 R14_Ch6 R15_Ch6 R16_Ch6 R17_Ch6 R18_Ch6 R19_Ch6 R20_Ch6 R21_Ch6 R22_Ch6 R23_Ch6 R24_Ch6 R25_Ch6 R26_Ch6 R27_Ch6 R28_Ch6 R29_Ch6 R30_Ch6 R31_Ch6 R32_Ch6 R33_Ch6 R34_Ch6 R35_Ch6 R36_Ch6 R37_Ch6 R38_Ch6 R39_Ch6 R40_Ch6 R41_Ch6 R43_Ch6 R44_Ch6 R45_Ch6 R46_Ch6 R47_Ch6 R48_Ch6 R49_Ch6 R50_Ch6 R51_Ch6 R52_Ch6 R53_Ch6 R61_Ch6 R62_Ch6 R63_Ch6 R64_Ch6 R65_Ch6 R66_Ch6 R67_Ch6 R68_Ch6 R69_Ch6 R70_Ch6 R71_Ch6 R72_Ch6 R73_Ch6 R74_Ch6 R75_Ch6 R76_Ch6 R77_Ch6 R78_Ch6 R79_Ch6 R93_Ch6 R95_Ch6 R96_Ch6 R97_Ch6 R98_Ch6 R99_Ch6 R100_Ch6 R101_Ch6 R102_Ch6 R103_Ch6 R104_Ch6 R105_Ch6 R107_Ch6 R110_Ch6 R111_Ch6 R113_Ch6 R114_Ch6 R115_Ch6 R116_Ch6 R117_Ch6 R118_Ch6 R119_Ch6 R120_Ch6 R121_Ch6 R122_Ch6 R123_Ch6 R124_Ch6 R125_Ch6 R126_Ch6 R127_Ch6 R128_Ch6 R129_Ch6 R130_Ch6 R131_Ch6 R132_Ch6 R133_Ch6 R134_Ch6 R138_Ch6 R139_Ch6 R140_Ch6 R141_Ch6 R142_Ch6 R143_Ch6 R144_Ch6 R145_Ch6 R146_Ch6 R147_Ch6 R148_Ch6 R149_Ch6 R150_Ch6 R151_Ch6 R152_Ch6 R153_Ch6 R154_Ch6 R155_Ch6 R158_Ch6 R159_Ch6 R160_Ch6 R161_Ch6 R162_Ch6 R164_Ch6 R165_Ch6 R166_Ch6 R167_Ch6 R168_Ch6 R169_Ch6 R170_Ch6 R171_Ch6 R172_Ch6 R173_Ch6 R174_Ch6 R175_Ch6 R176_Ch6 R185_Ch6 R186_Ch6 R192_Ch6 R193_Ch6 R204_Ch6 R216_Ch6 R217_Ch6 R218_Ch6 R219_Ch6 R220_Ch6 TP1_Ch6 TP2_Ch6 TP3_Ch6 TP4_Ch6 TP5_Ch6 TP6_Ch6 TP7_Ch6 TP8_Ch6 TP9_Ch6 TP10_Ch6 U1_Ch6 U2_Ch6 U3_Ch6 U4_Ch6 U5_Ch6 U6_Ch6 U9_Ch6 U10_Ch6 U17_Ch6 U18_Ch6 U19_Ch6 U20_Ch6 U21_Ch6 U22_Ch6 U24_Ch6 U29_Ch6 U30_Ch6 U32_Ch6
component class Ch5: C1_Ch5 C2_Ch5 C3_Ch5 C4_Ch5 C5_Ch5 C6_Ch5 C7_Ch5 C8_Ch5 C9_Ch5 C10_Ch5 C11_Ch5 C12_Ch5 C13_Ch5 C14_Ch5 C15_Ch5 C16_Ch5 C17_Ch5 C18_Ch5 C19_Ch5 C20_Ch5 C21_Ch5 C22_Ch5 C23_Ch5 C24_Ch5 C25_Ch5 C26_Ch5 C27_Ch5 C28_Ch5 C29_Ch5 C30_Ch5 C31_Ch5 C32_Ch5 C33_Ch5 C34_Ch5 C35_Ch5 C36_Ch5 C37_Ch5 C38_Ch5 C39_Ch5 C40_Ch5 C41_Ch5 C42_Ch5 C43_Ch5 C44_Ch5 C45_Ch5 C46_Ch5 C47_Ch5 C48_Ch5 C49_Ch5 C50_Ch5 C51_Ch5 C52_Ch5 C53_Ch5 C54_Ch5 C55_Ch5 C56_Ch5 C57_Ch5 C58_Ch5 C59_Ch5 C60_Ch5 C61_Ch5 C62_Ch5 C63_Ch5 C64_Ch5 C65_Ch5 C66_Ch5 C67_Ch5 C68_Ch5 C69_Ch5 C70_Ch5 C71_Ch5 C72_Ch5 C73_Ch5 C74_Ch5 C75_Ch5 C76_Ch5 C77_Ch5 C78_Ch5 C79_Ch5 C80_Ch5 C81_Ch5 C82_Ch5 C83_Ch5 C84_Ch5 C85_Ch5 C86_Ch5 C87_Ch5 C88_Ch5 C89_Ch5 C90_Ch5 C91_Ch5 C92_Ch5 C93_Ch5 C94_Ch5 C95_Ch5 C96_Ch5 C97_Ch5 C98_Ch5 C99_Ch5 C100_Ch5 C101_Ch5 C102_Ch5 C103_Ch5 C122_Ch5 C135_Ch5 C136_Ch5 C150_Ch5 C151_Ch5 C166_Ch5 C167_Ch5 CS+1_Ch5 CS-1_Ch5 D1_Ch5 D2_Ch5 D3_Ch5 D4_Ch5 D5_Ch5 D6_Ch5 D7_Ch5 D10_Ch5 F1_Ch5 J1_Ch5 J2_Ch5 J3_Ch5 L1_Ch5 L2_Ch5 Q1_Ch5 Q7_Ch5 R1_Ch5 R2_Ch5 R3_Ch5 R4_Ch5 R5_Ch5 R6_Ch5 R7_Ch5 R8_Ch5 R9_Ch5 R10_Ch5 R11_Ch5 R12_Ch5 R13_Ch5 R14_Ch5 R15_Ch5 R16_Ch5 R17_Ch5 R18_Ch5 R19_Ch5 R20_Ch5 R21_Ch5 R22_Ch5 R23_Ch5 R24_Ch5 R25_Ch5 R26_Ch5 R27_Ch5 R28_Ch5 R29_Ch5 R30_Ch5 R31_Ch5 R32_Ch5 R33_Ch5 R34_Ch5 R35_Ch5 R36_Ch5 R37_Ch5 R38_Ch5 R39_Ch5 R40_Ch5 R41_Ch5 R43_Ch5 R44_Ch5 R45_Ch5 R46_Ch5 R47_Ch5 R48_Ch5 R49_Ch5 R50_Ch5 R51_Ch5 R52_Ch5 R53_Ch5 R61_Ch5 R62_Ch5 R63_Ch5 R64_Ch5 R65_Ch5 R66_Ch5 R67_Ch5 R68_Ch5 R69_Ch5 R70_Ch5 R71_Ch5 R72_Ch5 R73_Ch5 R74_Ch5 R75_Ch5 R76_Ch5 R77_Ch5 R78_Ch5 R79_Ch5 R93_Ch5 R95_Ch5 R96_Ch5 R97_Ch5 R98_Ch5 R99_Ch5 R100_Ch5 R101_Ch5 R102_Ch5 R103_Ch5 R104_Ch5 R105_Ch5 R107_Ch5 R110_Ch5 R111_Ch5 R113_Ch5 R114_Ch5 R115_Ch5 R116_Ch5 R117_Ch5 R118_Ch5 R119_Ch5 R120_Ch5 R121_Ch5 R122_Ch5 R123_Ch5 R124_Ch5 R125_Ch5 R126_Ch5 R127_Ch5 R128_Ch5 R129_Ch5 R130_Ch5 R131_Ch5 R132_Ch5 R133_Ch5 R134_Ch5 R138_Ch5 R139_Ch5 R140_Ch5 R141_Ch5 R142_Ch5 R143_Ch5 R144_Ch5 R145_Ch5 R146_Ch5 R147_Ch5 R148_Ch5 R149_Ch5 R150_Ch5 R151_Ch5 R152_Ch5 R153_Ch5 R154_Ch5 R155_Ch5 R158_Ch5 R159_Ch5 R160_Ch5 R161_Ch5 R162_Ch5 R164_Ch5 R165_Ch5 R166_Ch5 R167_Ch5 R168_Ch5 R169_Ch5 R170_Ch5 R171_Ch5 R172_Ch5 R173_Ch5 R174_Ch5 R175_Ch5 R176_Ch5 R185_Ch5 R186_Ch5 R192_Ch5 R193_Ch5 R204_Ch5 R216_Ch5 R217_Ch5 R218_Ch5 R219_Ch5 R220_Ch5 TP1_Ch5 TP2_Ch5 TP3_Ch5 TP4_Ch5 TP5_Ch5 TP6_Ch5 TP7_Ch5 TP8_Ch5 TP9_Ch5 TP10_Ch5 U1_Ch5 U2_Ch5 U3_Ch5 U4_Ch5 U5_Ch5 U6_Ch5 U9_Ch5 U10_Ch5 U17_Ch5 U18_Ch5 U19_Ch5 U20_Ch5 U21_Ch5 U22_Ch5 U24_Ch5 U29_Ch5 U30_Ch5 U32_Ch5
component class Ch4: C1_Ch4 C2_Ch4 C3_Ch4 C4_Ch4 C5_Ch4 C6_Ch4 C7_Ch4 C8_Ch4 C9_Ch4 C10_Ch4 C11_Ch4 C12_Ch4 C13_Ch4 C14_Ch4 C15_Ch4 C16_Ch4 C17_Ch4 C18_Ch4 C19_Ch4 C20_Ch4 C21_Ch4 C22_Ch4 C23_Ch4 C24_Ch4 C25_Ch4 C26_Ch4 C27_Ch4 C28_Ch4 C29_Ch4 C30_Ch4 C31_Ch4 C32_Ch4 C33_Ch4 C34_Ch4 C35_Ch4 C36_Ch4 C37_Ch4 C38_Ch4 C39_Ch4 C40_Ch4 C41_Ch4 C42_Ch4 C43_Ch4 C44_Ch4 C45_Ch4 C46_Ch4 C47_Ch4 C48_Ch4 C49_Ch4 C50_Ch4 C51_Ch4 C52_Ch4 C53_Ch4 C54_Ch4 C55_Ch4 C56_Ch4 C57_Ch4 C58_Ch4 C59_Ch4 C60_Ch4 C61_Ch4 C62_Ch4 C63_Ch4 C64_Ch4 C65_Ch4 C66_Ch4 C67_Ch4 C68_Ch4 C69_Ch4 C70_Ch4 C71_Ch4 C72_Ch4 C73_Ch4 C74_Ch4 C75_Ch4 C76_Ch4 C77_Ch4 C78_Ch4 C79_Ch4 C80_Ch4 C81_Ch4 C82_Ch4 C83_Ch4 C84_Ch4 C85_Ch4 C86_Ch4 C87_Ch4 C88_Ch4 C89_Ch4 C90_Ch4 C91_Ch4 C92_Ch4 C93_Ch4 C94_Ch4 C95_Ch4 C96_Ch4 C97_Ch4 C98_Ch4 C99_Ch4 C100_Ch4 C101_Ch4 C102_Ch4 C103_Ch4 C122_Ch4 C135_Ch4 C136_Ch4 C150_Ch4 C151_Ch4 C166_Ch4 C167_Ch4 CS+1_Ch4 CS-1_Ch4 D1_Ch4 D2_Ch4 D3_Ch4 D4_Ch4 D5_Ch4 D6_Ch4 D7_Ch4 D10_Ch4 F1_Ch4 J1_Ch4 J2_Ch4 J3_Ch4 L1_Ch4 L2_Ch4 Q1_Ch4 Q7_Ch4 R1_Ch4 R2_Ch4 R3_Ch4 R4_Ch4 R5_Ch4 R6_Ch4 R7_Ch4 R8_Ch4 R9_Ch4 R10_Ch4 R11_Ch4 R12_Ch4 R13_Ch4 R14_Ch4 R15_Ch4 R16_Ch4 R17_Ch4 R18_Ch4 R19_Ch4 R20_Ch4 R21_Ch4 R22_Ch4 R23_Ch4 R24_Ch4 R25_Ch4 R26_Ch4 R27_Ch4 R28_Ch4 R29_Ch4 R30_Ch4 R31_Ch4 R32_Ch4 R33_Ch4 R34_Ch4 R35_Ch4 R36_Ch4 R37_Ch4 R38_Ch4 R39_Ch4 R40_Ch4 R41_Ch4 R43_Ch4 R44_Ch4 R45_Ch4 R46_Ch4 R47_Ch4 R48_Ch4 R49_Ch4 R50_Ch4 R51_Ch4 R52_Ch4 R53_Ch4 R61_Ch4 R62_Ch4 R63_Ch4 R64_Ch4 R65_Ch4 R66_Ch4 R67_Ch4 R68_Ch4 R69_Ch4 R70_Ch4 R71_Ch4 R72_Ch4 R73_Ch4 R74_Ch4 R75_Ch4 R76_Ch4 R77_Ch4 R78_Ch4 R79_Ch4 R93_Ch4 R95_Ch4 R96_Ch4 R97_Ch4 R98_Ch4 R99_Ch4 R100_Ch4 R101_Ch4 R102_Ch4 R103_Ch4 R104_Ch4 R105_Ch4 R107_Ch4 R110_Ch4 R111_Ch4 R113_Ch4 R114_Ch4 R115_Ch4 R116_Ch4 R117_Ch4 R118_Ch4 R119_Ch4 R120_Ch4 R121_Ch4 R122_Ch4 R123_Ch4 R124_Ch4 R125_Ch4 R126_Ch4 R127_Ch4 R128_Ch4 R129_Ch4 R130_Ch4 R131_Ch4 R132_Ch4 R133_Ch4 R134_Ch4 R138_Ch4 R139_Ch4 R140_Ch4 R141_Ch4 R142_Ch4 R143_Ch4 R144_Ch4 R145_Ch4 R146_Ch4 R147_Ch4 R148_Ch4 R149_Ch4 R150_Ch4 R151_Ch4 R152_Ch4 R153_Ch4 R154_Ch4 R155_Ch4 R158_Ch4 R159_Ch4 R160_Ch4 R161_Ch4 R162_Ch4 R164_Ch4 R165_Ch4 R166_Ch4 R167_Ch4 R168_Ch4 R169_Ch4 R170_Ch4 R171_Ch4 R172_Ch4 R173_Ch4 R174_Ch4 R175_Ch4 R176_Ch4 R185_Ch4 R186_Ch4 R192_Ch4 R193_Ch4 R204_Ch4 R216_Ch4 R217_Ch4 R218_Ch4 R219_Ch4 R220_Ch4 TP1_Ch4 TP2_Ch4 TP3_Ch4 TP4_Ch4 TP5_Ch4 TP6_Ch4 TP7_Ch4 TP8_Ch4 TP9_Ch4 TP10_Ch4 U1_Ch4 U2_Ch4 U3_Ch4 U4_Ch4 U5_Ch4 U6_Ch4 U9_Ch4 U10_Ch4 U17_Ch4 U18_Ch4 U19_Ch4 U20_Ch4 U21_Ch4 U22_Ch4 U24_Ch4 U29_Ch4 U30_Ch4 U32_Ch4
pad class "mounting hole": H1-1 H2-1 H3-1 H4-1 H5-1 H6-1 H7-0 H8-0 H9-0 H10-0 H11-0 H12-0 H13-1 H14-1 H15-0 H16-0 H17-1 H18-0
component class Ch3: C1_Ch3 C2_Ch3 C3_Ch3 C4_Ch3 C5_Ch3 C6_Ch3 C7_Ch3 C8_Ch3 C9_Ch3 C10_Ch3 C11_Ch3 C12_Ch3 C13_Ch3 C14_Ch3 C15_Ch3 C16_Ch3 C17_Ch3 C18_Ch3 C19_Ch3 C20_Ch3 C21_Ch3 C22_Ch3 C23_Ch3 C24_Ch3 C25_Ch3 C26_Ch3 C27_Ch3 C28_Ch3 C29_Ch3 C30_Ch3 C31_Ch3 C32_Ch3 C33_Ch3 C34_Ch3 C35_Ch3 C36_Ch3 C37_Ch3 C38_Ch3 C39_Ch3 C40_Ch3 C41_Ch3 C42_Ch3 C43_Ch3 C44_Ch3 C45_Ch3 C46_Ch3 C47_Ch3 C48_Ch3 C49_Ch3 C50_Ch3 C51_Ch3 C52_Ch3 C53_Ch3 C54_Ch3 C55_Ch3 C56_Ch3 C57_Ch3 C58_Ch3 C59_Ch3 C60_Ch3 C61_Ch3 C62_Ch3 C63_Ch3 C64_Ch3 C65_Ch3 C66_Ch3 C67_Ch3 C68_Ch3 C69_Ch3 C70_Ch3 C71_Ch3 C72_Ch3 C73_Ch3 C74_Ch3 C75_Ch3 C76_Ch3 C77_Ch3 C78_Ch3 C79_Ch3 C80_Ch3 C81_Ch3 C82_Ch3 C83_Ch3 C84_Ch3 C85_Ch3 C86_Ch3 C87_Ch3 C88_Ch3 C89_Ch3 C90_Ch3 C91_Ch3 C92_Ch3 C93_Ch3 C94_Ch3 C95_Ch3 C96_Ch3 C97_Ch3 C98_Ch3 C99_Ch3 C100_Ch3 C101_Ch3 C102_Ch3 C103_Ch3 C122_Ch3 C135_Ch3 C136_Ch3 C150_Ch3 C151_Ch3 C166_Ch3 C167_Ch3 CS+1_Ch3 CS-1_Ch3 D1_Ch3 D2_Ch3 D3_Ch3 D4_Ch3 D5_Ch3 D6_Ch3 D7_Ch3 D10_Ch3 F1_Ch3 J1_Ch3 J2_Ch3 J3_Ch3 L1_Ch3 L2_Ch3 Q1_Ch3 Q7_Ch3 R1_Ch3 R2_Ch3 R3_Ch3 R4_Ch3 R5_Ch3 R6_Ch3 R7_Ch3 R8_Ch3 R9_Ch3 R10_Ch3 R11_Ch3 R12_Ch3 R13_Ch3 R14_Ch3 R15_Ch3 R16_Ch3 R17_Ch3 R18_Ch3 R19_Ch3 R20_Ch3 R21_Ch3 R22_Ch3 R23_Ch3 R24_Ch3 R25_Ch3 R26_Ch3 R27_Ch3 R28_Ch3 R29_Ch3 R30_Ch3 R31_Ch3 R32_Ch3 R33_Ch3 R34_Ch3 R35_Ch3 R36_Ch3 R37_Ch3 R38_Ch3 R39_Ch3 R40_Ch3 R41_Ch3 R43_Ch3 R44_Ch3 R45_Ch3 R46_Ch3 R47_Ch3 R48_Ch3 R49_Ch3 R50_Ch3 R51_Ch3 R52_Ch3 R53_Ch3 R61_Ch3 R62_Ch3 R63_Ch3 R64_Ch3 R65_Ch3 R66_Ch3 R67_Ch3 R68_Ch3 R69_Ch3 R70_Ch3 R71_Ch3 R72_Ch3 R73_Ch3 R74_Ch3 R75_Ch3 R76_Ch3 R77_Ch3 R78_Ch3 R79_Ch3 R93_Ch3 R95_Ch3 R96_Ch3 R97_Ch3 R98_Ch3 R99_Ch3 R100_Ch3 R101_Ch3 R102_Ch3 R103_Ch3 R104_Ch3 R105_Ch3 R107_Ch3 R110_Ch3 R111_Ch3 R113_Ch3 R114_Ch3 R115_Ch3 R116_Ch3 R117_Ch3 R118_Ch3 R119_Ch3 R120_Ch3 R121_Ch3 R122_Ch3 R123_Ch3 R124_Ch3 R125_Ch3 R126_Ch3 R127_Ch3 R128_Ch3 R129_Ch3 R130_Ch3 R131_Ch3 R132_Ch3 R133_Ch3 R134_Ch3 R138_Ch3 R139_Ch3 R140_Ch3 R141_Ch3 R142_Ch3 R143_Ch3 R144_Ch3 R145_Ch3 R146_Ch3 R147_Ch3 R148_Ch3 R149_Ch3 R150_Ch3 R151_Ch3 R152_Ch3 R153_Ch3 R154_Ch3 R155_Ch3 R158_Ch3 R159_Ch3 R160_Ch3 R161_Ch3 R162_Ch3 R164_Ch3 R165_Ch3 R166_Ch3 R167_Ch3 R168_Ch3 R169_Ch3 R170_Ch3 R171_Ch3 R172_Ch3 R173_Ch3 R174_Ch3 R175_Ch3 R176_Ch3 R185_Ch3 R186_Ch3 R192_Ch3 R193_Ch3 R204_Ch3 R216_Ch3 R217_Ch3 R218_Ch3 R219_Ch3 R220_Ch3 TP1_Ch3 TP2_Ch3 TP3_Ch3 TP4_Ch3 TP5_Ch3 TP6_Ch3 TP7_Ch3 TP8_Ch3 TP9_Ch3 TP10_Ch3 U1_Ch3 U2_Ch3 U3_Ch3 U4_Ch3 U5_Ch3 U6_Ch3 U9_Ch3 U10_Ch3 U17_Ch3 U18_Ch3 U19_Ch3 U20_Ch3 U21_Ch3 U22_Ch3 U24_Ch3 U29_Ch3 U30_Ch3 U32_Ch3
component class Ch2: C1_Ch2 C2_Ch2 C3_Ch2 C4_Ch2 C5_Ch2 C6_Ch2 C7_Ch2 C8_Ch2 C9_Ch2 C10_Ch2 C11_Ch2 C12_Ch2 C13_Ch2 C14_Ch2 C15_Ch2 C16_Ch2 C17_Ch2 C18_Ch2 C19_Ch2 C20_Ch2 C21_Ch2 C22_Ch2 C23_Ch2 C24_Ch2 C25_Ch2 C26_Ch2 C27_Ch2 C28_Ch2 C29_Ch2 C30_Ch2 C31_Ch2 C32_Ch2 C33_Ch2 C34_Ch2 C35_Ch2 C36_Ch2 C37_Ch2 C38_Ch2 C39_Ch2 C40_Ch2 C41_Ch2 C42_Ch2 C43_Ch2 C44_Ch2 C45_Ch2 C46_Ch2 C47_Ch2 C48_Ch2 C49_Ch2 C50_Ch2 C51_Ch2 C52_Ch2 C53_Ch2 C54_Ch2 C55_Ch2 C56_Ch2 C57_Ch2 C58_Ch2 C59_Ch2 C60_Ch2 C61_Ch2 C62_Ch2 C63_Ch2 C64_Ch2 C65_Ch2 C66_Ch2 C67_Ch2 C68_Ch2 C69_Ch2 C70_Ch2 C71_Ch2 C72_Ch2 C73_Ch2 C74_Ch2 C75_Ch2 C76_Ch2 C77_Ch2 C78_Ch2 C79_Ch2 C80_Ch2 C81_Ch2 C82_Ch2 C83_Ch2 C84_Ch2 C85_Ch2 C86_Ch2 C87_Ch2 C88_Ch2 C89_Ch2 C90_Ch2 C91_Ch2 C92_Ch2 C93_Ch2 C94_Ch2 C95_Ch2 C96_Ch2 C97_Ch2 C98_Ch2 C99_Ch2 C100_Ch2 C101_Ch2 C102_Ch2 C103_Ch2 C122_Ch2 C135_Ch2 C136_Ch2 C150_Ch2 C151_Ch2 C166_Ch2 C167_Ch2 CS+1_Ch2 CS-1_Ch2 D1_Ch2 D2_Ch2 D3_Ch2 D4_Ch2 D5_Ch2 D6_Ch2 D7_Ch2 D10_Ch2 F1_Ch2 J1_Ch2 J2_Ch2 J3_Ch2 L1_Ch2 L2_Ch2 Q1_Ch2 Q7_Ch2 R1_Ch2 R2_Ch2 R3_Ch2 R4_Ch2 R5_Ch2 R6_Ch2 R7_Ch2 R8_Ch2 R9_Ch2 R10_Ch2 R11_Ch2 R12_Ch2 R13_Ch2 R14_Ch2 R15_Ch2 R16_Ch2 R17_Ch2 R18_Ch2 R19_Ch2 R20_Ch2 R21_Ch2 R22_Ch2 R23_Ch2 R24_Ch2 R25_Ch2 R26_Ch2 R27_Ch2 R28_Ch2 R29_Ch2 R30_Ch2 R31_Ch2 R32_Ch2 R33_Ch2 R34_Ch2 R35_Ch2 R36_Ch2 R37_Ch2 R38_Ch2 R39_Ch2 R40_Ch2 R41_Ch2 R43_Ch2 R44_Ch2 R45_Ch2 R46_Ch2 R47_Ch2 R48_Ch2 R49_Ch2 R50_Ch2 R51_Ch2 R52_Ch2 R53_Ch2 R61_Ch2 R62_Ch2 R63_Ch2 R64_Ch2 R65_Ch2 R66_Ch2 R67_Ch2 R68_Ch2 R69_Ch2 R70_Ch2 R71_Ch2 R72_Ch2 R73_Ch2 R74_Ch2 R75_Ch2 R76_Ch2 R77_Ch2 R78_Ch2 R79_Ch2 R93_Ch2 R95_Ch2 R96_Ch2 R97_Ch2 R98_Ch2 R99_Ch2 R100_Ch2 R101_Ch2 R102_Ch2 R103_Ch2 R104_Ch2 R105_Ch2 R107_Ch2 R110_Ch2 R111_Ch2 R113_Ch2 R114_Ch2 R115_Ch2 R116_Ch2 R117_Ch2 R118_Ch2 R119_Ch2 R120_Ch2 R121_Ch2 R122_Ch2 R123_Ch2 R124_Ch2 R125_Ch2 R126_Ch2 R127_Ch2 R128_Ch2 R129_Ch2 R130_Ch2 R131_Ch2 R132_Ch2 R133_Ch2 R134_Ch2 R138_Ch2 R139_Ch2 R140_Ch2 R141_Ch2 R142_Ch2 R143_Ch2 R144_Ch2 R145_Ch2 R146_Ch2 R147_Ch2 R148_Ch2 R149_Ch2 R150_Ch2 R151_Ch2 R152_Ch2 R153_Ch2 R154_Ch2 R155_Ch2 R158_Ch2 R159_Ch2 R160_Ch2 R161_Ch2 R162_Ch2 R164_Ch2 R165_Ch2 R166_Ch2 R167_Ch2 R168_Ch2 R169_Ch2 R170_Ch2 R171_Ch2 R172_Ch2 R173_Ch2 R174_Ch2 R175_Ch2 R176_Ch2 R185_Ch2 R186_Ch2 R192_Ch2 R193_Ch2 R204_Ch2 R216_Ch2 R217_Ch2 R218_Ch2 R219_Ch2 R220_Ch2 TP1_Ch2 TP2_Ch2 TP3_Ch2 TP4_Ch2 TP5_Ch2 TP6_Ch2 TP7_Ch2 TP8_Ch2 TP9_Ch2 TP10_Ch2 U1_Ch2 U2_Ch2 U3_Ch2 U4_Ch2 U5_Ch2 U6_Ch2 U9_Ch2 U10_Ch2 U17_Ch2 U18_Ch2 U19_Ch2 U20_Ch2 U21_Ch2 U22_Ch2 U24_Ch2 U29_Ch2 U30_Ch2 U32_Ch2
component class Ch1: C1_Ch1 C2_Ch1 C3_Ch1 C4_Ch1 C5_Ch1 C6_Ch1 C7_Ch1 C8_Ch1 C9_Ch1 C10_Ch1 C11_Ch1 C12_Ch1 C13_Ch1 C14_Ch1 C15_Ch1 C16_Ch1 C17_Ch1 C18_Ch1 C19_Ch1 C20_Ch1 C21_Ch1 C22_Ch1 C23_Ch1 C24_Ch1 C25_Ch1 C26_Ch1 C27_Ch1 C28_Ch1 C29_Ch1 C30_Ch1 C31_Ch1 C32_Ch1 C33_Ch1 C34_Ch1 C35_Ch1 C36_Ch1 C37_Ch1 C38_Ch1 C39_Ch1 C40_Ch1 C41_Ch1 C42_Ch1 C43_Ch1 C44_Ch1 C45_Ch1 C46_Ch1 C47_Ch1 C48_Ch1 C49_Ch1 C50_Ch1 C51_Ch1 C52_Ch1 C53_Ch1 C54_Ch1 C55_Ch1 C56_Ch1 C57_Ch1 C58_Ch1 C59_Ch1 C60_Ch1 C61_Ch1 C62_Ch1 C63_Ch1 C64_Ch1 C65_Ch1 C66_Ch1 C67_Ch1 C68_Ch1 C69_Ch1 C70_Ch1 C71_Ch1 C72_Ch1 C73_Ch1 C74_Ch1 C75_Ch1 C76_Ch1 C77_Ch1 C78_Ch1 C79_Ch1 C80_Ch1 C81_Ch1 C82_Ch1 C83_Ch1 C84_Ch1 C85_Ch1 C86_Ch1 C87_Ch1 C88_Ch1 C89_Ch1 C90_Ch1 C91_Ch1 C92_Ch1 C93_Ch1 C94_Ch1 C95_Ch1 C96_Ch1 C97_Ch1 C98_Ch1 C99_Ch1 C100_Ch1 C101_Ch1 C102_Ch1 C103_Ch1 C122_Ch1 C135_Ch1 C136_Ch1 C150_Ch1 C151_Ch1 C166_Ch1 C167_Ch1 CS+1_Ch1 CS-1_Ch1 D1_Ch1 D2_Ch1 D3_Ch1 D4_Ch1 D5_Ch1 D6_Ch1 D7_Ch1 D10_Ch1 F1_Ch1 J1_Ch1 J2_Ch1 J3_Ch1 L1_Ch1 L2_Ch1 Q1_Ch1 Q7_Ch1 R1_Ch1 R2_Ch1 R3_Ch1 R4_Ch1 R5_Ch1 R6_Ch1 R7_Ch1 R8_Ch1 R9_Ch1 R10_Ch1 R11_Ch1 R12_Ch1 R13_Ch1 R14_Ch1 R15_Ch1 R16_Ch1 R17_Ch1 R18_Ch1 R19_Ch1 R20_Ch1 R21_Ch1 R22_Ch1 R23_Ch1 R24_Ch1 R25_Ch1 R26_Ch1 R27_Ch1 R28_Ch1 R29_Ch1 R30_Ch1 R31_Ch1 R32_Ch1 R33_Ch1 R34_Ch1 R35_Ch1 R36_Ch1 R37_Ch1 R38_Ch1 R39_Ch1 R40_Ch1 R41_Ch1 R43_Ch1 R44_Ch1 R45_Ch1 R46_Ch1 R47_Ch1 R48_Ch1 R49_Ch1 R50_Ch1 R51_Ch1 R52_Ch1 R53_Ch1 R61_Ch1 R62_Ch1 R63_Ch1 R64_Ch1 R65_Ch1 R66_Ch1 R67_Ch1 R68_Ch1 R69_Ch1 R70_Ch1 R71_Ch1 R72_Ch1 R73_Ch1 R74_Ch1 R75_Ch1 R76_Ch1 R77_Ch1 R78_Ch1 R79_Ch1 R93_Ch1 R95_Ch1 R96_Ch1 R97_Ch1 R98_Ch1 R99_Ch1 R100_Ch1 R101_Ch1 R102_Ch1 R103_Ch1 R104_Ch1 R105_Ch1 R107_Ch1 R110_Ch1 R111_Ch1 R113_Ch1 R114_Ch1 R115_Ch1 R116_Ch1 R117_Ch1 R118_Ch1 R119_Ch1 R120_Ch1 R121_Ch1 R122_Ch1 R123_Ch1 R124_Ch1 R125_Ch1 R126_Ch1 R127_Ch1 R128_Ch1 R129_Ch1 R130_Ch1 R131_Ch1 R132_Ch1 R133_Ch1 R134_Ch1 R138_Ch1 R139_Ch1 R140_Ch1 R141_Ch1 R142_Ch1 R143_Ch1 R144_Ch1 R145_Ch1 R146_Ch1 R147_Ch1 R148_Ch1 R149_Ch1 R150_Ch1 R151_Ch1 R152_Ch1 R153_Ch1 R154_Ch1 R155_Ch1 R158_Ch1 R159_Ch1 R160_Ch1 R161_Ch1 R162_Ch1 R164_Ch1 R165_Ch1 R166_Ch1 R167_Ch1 R168_Ch1 R169_Ch1 R170_Ch1 R171_Ch1 R172_Ch1 R173_Ch1 R174_Ch1 R175_Ch1 R176_Ch1 R185_Ch1 R186_Ch1 R192_Ch1 R193_Ch1 R204_Ch1 R216_Ch1 R217_Ch1 R218_Ch1 R219_Ch1 R220_Ch1 TP1_Ch1 TP2_Ch1 TP3_Ch1 TP4_Ch1 TP5_Ch1 TP6_Ch1 TP7_Ch1 TP8_Ch1 TP9_Ch1 TP10_Ch1 U1_Ch1 U2_Ch1 U3_Ch1 U4_Ch1 U5_Ch1 U6_Ch1 U9_Ch1 U10_Ch1 U17_Ch1 U18_Ch1 U19_Ch1 U20_Ch1 U21_Ch1 U22_Ch1 U24_Ch1 U29_Ch1 U30_Ch1 U32_Ch1
component class "Bias Power Supply": C28 C30 C32 C34 C38 C40 C42 C102 C103 C104 C105 C106 C107 C108 C109 C110 C111 C112 C113 C114 C115 C116 C117 C118 C119 C120 C121 C129 C130 C131 C132 C133 C134 C137 C138 C139 C140 C141 C142 C143 C146 C147 C152 C153 C154 C155 C156 C157 C158 C159 C160 C161 C162 C163 C164 C165 D1 D3 D9 D10 D11 D13 D14 D15 D17 D18 J4 L3 L4 L5 L6 NT1 Q5 Q6 R163 R176 R178 R179 R180 R182 R183 R184 R188 R189 R190 R191 R194 R195 R196 R197 R198 R199 R200 R201 R202 R203 R205 R206 R207 R208 R209 R210 R211 R212 R213 R214 R215 S3 SH-J4 TP2 TP3 TP4 TP5 TP6 TP24 TP25 TP26 TP27 TP28 TP29 TP30 TP31 TP32 TP33 TP34 TP35 TP36 U7 U8 U20 U21 U22 U23 U25 U31
component class Hardware: FID1 FID2 FID3 FID4 FID5 FID6 H1 H2 H3 H4 H5 H6 H7 H8 H9 H10 H11 H12 H13 H14 H15 H16 H17 H18 LBL1 Logo1 Logo3 Logo4 LOGO5 Logo6 Logo7 ZZ1 ZZ2 ZZ3 ZZ4
differential pair R_CS_CH1: +NetR7_Ch1_4 -NetR7_Ch1_3
differential pair VSense_CH8: +B+_Ch8 -B-_Ch8
differential pair VSense_CH7: +B+_Ch7 -B-_Ch7
differential pair VSense_CH6: +B+_Ch6 -B-_Ch6
differential pair VSense_CH5: +B+_Ch5 -B-_Ch5
differential pair VSense_CH4: +B+_Ch4 -B-_Ch4
differential pair VSense_CH3: +B+_Ch3 -B-_Ch3
differential pair VSense_CH2: +B+_Ch2 -B-_Ch2
differential pair VSense_CH1: +B+_Ch1 -B-_Ch1
differential pair CS_CH8: +CS+_Ch8 -CS-_Ch8
differential pair CS_CH7: +CS+_Ch7 -CS-_Ch7
differential pair CS_CH6: +CS+_Ch6 -CS-_Ch6
differential pair CS_CH5: +CS+_Ch5 -CS-_Ch5
differential pair CS_CH4: +CS+_Ch4 -CS-_Ch4
differential pair CS_CH3: +CS+_Ch3 -CS-_Ch3
differential pair CS_CH2: +CS+_Ch2 -CS-_Ch2
differential pair CS_CH1: +CS+_Ch1 -CS-_Ch1
differential pair Ch8_Vout8: +NetC50_Ch8_1 -NetC50_Ch8_2
differential pair Ch8_Iout8: +NetC27_Ch8_1 -NetC27_Ch8_2
differential pair Ch7_Vout7: +NetC50_Ch7_1 -NetC50_Ch7_2
differential pair Ch7_Iout7: +NetC27_Ch7_1 -NetC27_Ch7_2
differential pair Ch6_Vout6: +NetC50_Ch6_1 -NetC50_Ch6_2
differential pair Ch6_Iout6: +NetC27_Ch6_1 -NetC27_Ch6_2
differential pair Ch5_Vout5: +NetC50_Ch5_1 -NetC50_Ch5_2
differential pair Ch5_Iout5: +NetC27_Ch5_1 -NetC27_Ch5_2
differential pair Ch4_Vout4: +NetC50_Ch4_1 -NetC50_Ch4_2
differential pair Ch4_Iout4: +NetC27_Ch4_1 -NetC27_Ch4_2
differential pair Ch3_Vout3: +NetC50_Ch3_1 -NetC50_Ch3_2
differential pair Ch3_Iout3: +NetC27_Ch3_1 -NetC27_Ch3_2
differential pair Ch2_Vout2: +NetC50_Ch2_1 -NetC50_Ch2_2
differential pair Ch2_Iout2: +NetC27_Ch2_1 -NetC27_Ch2_2
differential pair Ch1_Vout1: +NetC50_Ch1_1 -NetC50_Ch1_2
differential pair Ch1_Iout1: +NetC27_Ch1_1 -NetC27_Ch1_2
differential pair ADC_Vout8: +NetC92_2 -NetC92_1
differential pair ADC_Iout8: +NetC89_1 -NetC89_2
differential pair ADC_Vout7: +NetC88_2 -NetC88_1
differential pair ADC_Iout7: +NetC87_1 -NetC87_2
differential pair ADC_Vout6: +NetC86_2 -NetC86_1
differential pair ADC_Iout6: +NetC84_1 -NetC84_2
differential pair ADC_Vout5: +NetC82_2 -NetC82_1
differential pair ADC_Iout5: +NetC81_1 -NetC81_2
differential pair ADC_Vout4: +NetC71_2 -NetC71_1
differential pair ADC_Iout4: +NetC68_1 -NetC68_2
differential pair ADC_Vout3: +NetC67_2 -NetC67_1
differential pair ADC_Iout3: +NetC66_1 -NetC66_2
differential pair ADC_Vout2: +NetC65_2 -NetC65_1
differential pair ADC_Iout2: +NetC63_1 -NetC63_2
differential pair ADC_Vout1: +NetC61_2 -NetC61_1
differential pair ADC_Iout1: +NetC60_1 -NetC60_2
differential pair Vout8: +VoutP8 -VoutN8
differential pair Vout7: +VoutP7 -VoutN7
differential pair Vout6: +VoutP6 -VoutN6
differential pair Vout5: +VoutP5 -VoutN5
differential pair Vout4: +VoutP4 -VoutN4
differential pair Vout3: +VoutP3 -VoutN3
differential pair Vout2: +VoutP2 -VoutN2
differential pair Vout1: +VoutP1 -VoutN1
differential pair Iout8: +IoutP8 -IoutN8
differential pair Iout7: +IoutP7 -IoutN7
differential pair Iout6: +IoutP6 -IoutN6
differential pair Iout5: +IoutP5 -IoutN5
differential pair Iout4: +IoutP4 -IoutN4
differential pair Iout3: +IoutP3 -IoutN3
differential pair Iout2: +IoutP2 -IoutN2
differential pair Iout1: +IoutP1 -IoutN1

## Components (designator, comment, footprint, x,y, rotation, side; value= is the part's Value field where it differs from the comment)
C1_Ch1 "C0603C104J3RACTU" 0603L 1962.33,3574.31 r90 top value=0.1uF (schematic designator C1)
C1_Ch2 "C0603C104J3RACTU" 0603L 3524.33,3574.23 r90 top value=0.1uF (schematic designator C1)
C1_Ch3 "C0603C104J3RACTU" 0603L 5086.33,3574.15 r90 top value=0.1uF (schematic designator C1)
C1_Ch4 "C0603C104J3RACTU" 0603L 6648.33,3574.07 r90 top value=0.1uF (schematic designator C1)
C1_Ch5 "C0603C104J3RACTU" 0603L 8604.03,3573.99 r90 top value=0.1uF (schematic designator C1)
C1_Ch6 "C0603C104J3RACTU" 0603L 10166.03,3573.91 r90 top value=0.1uF (schematic designator C1)
C1_Ch7 "C0603C104J3RACTU" 0603L 11728.03,3573.83 r90 top value=0.1uF (schematic designator C1)
C1_Ch8 "C0603C104J3RACTU" 0603L 13290.03,3573.76 r90 top value=0.1uF (schematic designator C1)
C2_Ch1 "GRM1885C1H101JA01D" 0603L 2485,3442 r180 bottom value=100pF (schematic designator C2)
C2_Ch2 "GRM1885C1H101JA01D" 0603L 4047,3441.92 r180 bottom value=100pF (schematic designator C2)
C2_Ch3 "GRM1885C1H101JA01D" 0603L 5609,3441.84 r180 bottom value=100pF (schematic designator C2)
C2_Ch4 "GRM1885C1H101JA01D" 0603L 7171,3441.76 r180 bottom value=100pF (schematic designator C2)
C2_Ch5 "GRM1885C1H101JA01D" 0603L 9126.7,3441.69 r180 bottom value=100pF (schematic designator C2)
C2_Ch6 "GRM1885C1H101JA01D" 0603L 10688.7,3441.61 r180 bottom value=100pF (schematic designator C2)
C2_Ch7 "GRM1885C1H101JA01D" 0603L 12250.7,3441.53 r180 bottom value=100pF (schematic designator C2)
C2_Ch8 "GRM1885C1H101JA01D" 0603L 13812.7,3441.45 r180 bottom value=100pF (schematic designator C2)
C3_Ch1 "35SVPK330M" CAPSMT_62_F12 2390,3940 r0 top value=330uF (schematic designator C3)
C3_Ch2 "35SVPK330M" CAPSMT_62_F12 3952,3939.92 r0 top value=330uF (schematic designator C3)
C3_Ch3 "35SVPK330M" CAPSMT_62_F12 5514,3939.84 r0 top value=330uF (schematic designator C3)
C3_Ch4 "35SVPK330M" CAPSMT_62_F12 7076,3939.76 r0 top value=330uF (schematic designator C3)
C3_Ch5 "35SVPK330M" CAPSMT_62_F12 9031.7,3939.69 r0 top value=330uF (schematic designator C3)
C3_Ch6 "35SVPK330M" CAPSMT_62_F12 10593.7,3939.61 r0 top value=330uF (schematic designator C3)
C3_Ch7 "35SVPK330M" CAPSMT_62_F12 12155.7,3939.53 r0 top value=330uF (schematic designator C3)
C3_Ch8 "35SVPK330M" CAPSMT_62_F12 13717.7,3939.45 r0 top value=330uF (schematic designator C3)
C4_Ch1 "GRM32ER71E226KE15L" 1210_270 2350,3633 r0 top value=22uF (schematic designator C4)
C4_Ch2 "GRM32ER71E226KE15L" 1210_270 3912,3632.92 r0 top value=22uF (schematic designator C4)
C4_Ch3 "GRM32ER71E226KE15L" 1210_270 5474,3632.84 r0 top value=22uF (schematic designator C4)
C4_Ch4 "GRM32ER71E226KE15L" 1210_270 7036,3632.76 r0 top value=22uF (schematic designator C4)
C4_Ch5 "GRM32ER71E226KE15L" 1210_270 8991.7,3632.69 r0 top value=22uF (schematic designator C4)
C4_Ch6 "GRM32ER71E226KE15L" 1210_270 10553.7,3632.61 r0 top value=22uF (schematic designator C4)
C4_Ch7 "GRM32ER71E226KE15L" 1210_270 12115.7,3632.53 r0 top value=22uF (schematic designator C4)
C4_Ch8 "GRM32ER71E226KE15L" 1210_270 13677.7,3632.45 r0 top value=22uF (schematic designator C4)
C5_Ch1 "GRM32ER71E226KE15L" 1210_270 2350,3633 r0 bottom value=22uF (schematic designator C5)
C5_Ch2 "GRM32ER71E226KE15L" 1210_270 3912,3632.92 r0 bottom value=22uF (schematic designator C5)
C5_Ch3 "GRM32ER71E226KE15L" 1210_270 5474,3632.84 r0 bottom value=22uF (schematic designator C5)
C5_Ch4 "GRM32ER71E226KE15L" 1210_270 7036,3632.76 r0 bottom value=22uF (schematic designator C5)
C5_Ch5 "GRM32ER71E226KE15L" 1210_270 8991.7,3632.69 r0 bottom value=22uF (schematic designator C5)
C5_Ch6 "GRM32ER71E226KE15L" 1210_270 10553.7,3632.61 r0 bottom value=22uF (schematic designator C5)
C5_Ch7 "GRM32ER71E226KE15L" 1210_270 12115.7,3632.53 r0 bottom value=22uF (schematic designator C5)
C5_Ch8 "GRM32ER71E226KE15L" 1210_270 13677.7,3632.45 r0 bottom value=22uF (schematic designator C5)
C6_Ch1 "GRM32ER71E226KE15L" 1210_270 2350,3770 r0 bottom value=22uF (schematic designator C6)
C6_Ch2 "GRM32ER71E226KE15L" 1210_270 3912,3769.92 r0 bottom value=22uF (schematic designator C6)
C6_Ch3 "GRM32ER71E226KE15L" 1210_270 5474,3769.84 r0 bottom value=22uF (schematic designator C6)
C6_Ch4 "GRM32ER71E226KE15L" 1210_270 7036,3769.76 r0 bottom value=22uF (schematic designator C6)
C6_Ch5 "GRM32ER71E226KE15L" 1210_270 8991.7,3769.69 r0 bottom value=22uF (schematic designator C6)
C6_Ch6 "GRM32ER71E226KE15L" 1210_270 10553.7,3769.61 r0 bottom value=22uF (schematic designator C6)
C6_Ch7 "GRM32ER71E226KE15L" 1210_270 12115.7,3769.53 r0 bottom value=22uF (schematic designator C6)
C6_Ch8 "GRM32ER71E226KE15L" 1210_270 13677.7,3769.45 r0 bottom value=22uF (schematic designator C6)
C7_Ch1 "Capacitor" 0603 2346,3873 r0 bottom value=0.1uF (schematic designator C7)
C7_Ch2 "Capacitor" 0603 3908,3872.92 r0 bottom value=0.1uF (schematic designator C7)
C7_Ch3 "Capacitor" 0603 5470,3872.84 r0 bottom value=0.1uF (schematic designator C7)
C7_Ch4 "Capacitor" 0603 7032,3872.76 r0 bottom value=0.1uF (schematic designator C7)
C7_Ch5 "Capacitor" 0603 8987.7,3872.69 r0 bottom value=0.1uF (schematic designator C7)
C7_Ch6 "Capacitor" 0603 10549.7,3872.61 r0 bottom value=0.1uF (schematic designator C7)
C7_Ch7 "Capacitor" 0603 12111.7,3872.53 r0 bottom value=0.1uF (schematic designator C7)
C7_Ch8 "Capacitor" 0603 13673.7,3872.45 r0 bottom value=0.1uF (schematic designator C7)
C8_Ch1 "C0603C105K3RACTU" 0603L 1962.33,3771.26 r270 top value=1uF (schematic designator C8)
C8_Ch2 "C0603C105K3RACTU" 0603L 3524.33,3771.18 r270 top value=1uF (schematic designator C8)
C8_Ch3 "C0603C105K3RACTU" 0603L 5086.33,3771.1 r270 top value=1uF (schematic designator C8)
C8_Ch4 "C0603C105K3RACTU" 0603L 6648.33,3771.02 r270 top value=1uF (schematic designator C8)
C8_Ch5 "C0603C105K3RACTU" 0603L 8604.03,3770.94 r270 top value=1uF (schematic designator C8)
C8_Ch6 "C0603C105K3RACTU" 0603L 10166.03,3770.86 r270 top value=1uF (schematic designator C8)
C8_Ch7 "C0603C105K3RACTU" 0603L 11728.03,3770.79 r270 top value=1uF (schematic designator C8)
C8_Ch8 "C0603C105K3RACTU" 0603L 13290.03,3770.71 r270 top value=1uF (schematic designator C8)
C9_Ch1 "20SVF560M" SM_RADIAL_10AMM 2665,1909 r0 top value=560uF (schematic designator C9)
C9_Ch2 "20SVF560M" SM_RADIAL_10AMM 4227,1908.92 r0 top value=560uF (schematic designator C9)
C9_Ch3 "20SVF560M" SM_RADIAL_10AMM 5789,1908.84 r0 top value=560uF (schematic designator C9)
C9_Ch4 "20SVF560M" SM_RADIAL_10AMM 7351,1908.76 r0 top value=560uF (schematic designator C9)
C9_Ch5 "20SVF560M" SM_RADIAL_10AMM 9306.7,1908.69 r0 top value=560uF (schematic designator C9)
C9_Ch6 "20SVF560M" SM_RADIAL_10AMM 10868.7,1908.61 r0 top value=560uF (schematic designator C9)
C9_Ch7 "20SVF560M" SM_RADIAL_10AMM 12430.7,1908.53 r0 top value=560uF (schematic designator C9)
C9_Ch8 "20SVF560M" SM_RADIAL_10AMM 13992.7,1908.45 r0 top value=560uF (schematic designator C9)
C10_Ch1 "20SVF560M" SM_RADIAL_10AMM 2665,1909 r0 bottom value=560uF (schematic designator C10)
C10_Ch2 "20SVF560M" SM_RADIAL_10AMM 4227,1908.92 r0 bottom value=560uF (schematic designator C10)
C10_Ch3 "20SVF560M" SM_RADIAL_10AMM 5789,1908.84 r0 bottom value=560uF (schematic designator C10)
C10_Ch4 "20SVF560M" SM_RADIAL_10AMM 7351,1908.76 r0 bottom value=560uF (schematic designator C10)
C10_Ch5 "20SVF560M" SM_RADIAL_10AMM 9306.7,1908.69 r0 bottom value=560uF (schematic designator C10)
C10_Ch6 "20SVF560M" SM_RADIAL_10AMM 10868.7,1908.61 r0 bottom value=560uF (schematic designator C10)
C10_Ch7 "20SVF560M" SM_RADIAL_10AMM 12430.7,1908.53 r0 bottom value=560uF (schematic designator C10)
C10_Ch8 "20SVF560M" SM_RADIAL_10AMM 13992.7,1908.45 r0 bottom value=560uF (schematic designator C10)
C11_Ch1 "Capacitor" 0603 2669,1517 r0 top value=0.1uF (schematic designator C11)
C11_Ch2 "Capacitor" 0603 4231,1516.92 r0 top value=0.1uF (schematic designator C11)
C11_Ch3 "Capacitor" 0603 5793,1516.84 r0 top value=0.1uF (schematic designator C11)
C11_Ch4 "Capacitor" 0603 7355,1516.76 r0 top value=0.1uF (schematic designator C11)
C11_Ch5 "Capacitor" 0603 9310.7,1516.69 r0 top value=0.1uF (schematic designator C11)
C11_Ch6 "Capacitor" 0603 10872.7,1516.61 r0 top value=0.1uF (schematic designator C11)
C11_Ch7 "Capacitor" 0603 12434.7,1516.53 r0 top value=0.1uF (schematic designator C11)
C11_Ch8 "Capacitor" 0603 13996.7,1516.45 r0 top value=0.1uF (schematic designator C11)
C12_Ch1 "GRM32ER71A476ME15L" 1210_270 2672,1624 r0 top value=47uF (schematic designator C12)
C12_Ch2 "GRM32ER71A476ME15L" 1210_270 4234,1623.92 r0 top value=47uF (schematic designator C12)
C12_Ch3 "GRM32ER71A476ME15L" 1210_270 5796,1623.84 r0 top value=47uF (schematic designator C12)
C12_Ch4 "GRM32ER71A476ME15L" 1210_270 7358,1623.76 r0 top value=47uF (schematic designator C12)
C12_Ch5 "GRM32ER71A476ME15L" 1210_270 9313.7,1623.69 r0 top value=47uF (schematic designator C12)
C12_Ch6 "GRM32ER71A476ME15L" 1210_270 10875.7,1623.61 r0 top value=47uF (schematic designator C12)
C12_Ch7 "GRM32ER71A476ME15L" 1210_270 12437.7,1623.53 r0 top value=47uF (schematic designator C12)
C12_Ch8 "GRM32ER71A476ME15L" 1210_270 13999.7,1623.45 r0 top value=47uF (schematic designator C12)
C13_Ch1 "GRM32ER71A476ME15L" 1210_270 2672,1624 r0 bottom value=47uF (schematic designator C13)
C13_Ch2 "GRM32ER71A476ME15L" 1210_270 4234,1623.92 r0 bottom value=47uF (schematic designator C13)
C13_Ch3 "GRM32ER71A476ME15L" 1210_270 5796,1623.84 r0 bottom value=47uF (schematic designator C13)
C13_Ch4 "GRM32ER71A476ME15L" 1210_270 7358,1623.76 r0 bottom value=47uF (schematic designator C13)
C13_Ch5 "GRM32ER71A476ME15L" 1210_270 9313.7,1623.69 r0 bottom value=47uF (schematic designator C13)
C13_Ch6 "GRM32ER71A476ME15L" 1210_270 10875.7,1623.61 r0 bottom value=47uF (schematic designator C13)
C13_Ch7 "GRM32ER71A476ME15L" 1210_270 12437.7,1623.53 r0 bottom value=47uF (schematic designator C13)
C13_Ch8 "GRM32ER71A476ME15L" 1210_270 13999.7,1623.45 r0 bottom value=47uF (schematic designator C13)
C14_Ch1 "C0603C104J3RACTU" 0603L 1657,3587 r180 bottom value=0.1uF (schematic designator C14)
C14_Ch2 "C0603C104J3RACTU" 0603L 3219,3586.92 r180 bottom value=0.1uF (schematic designator C14)
C14_Ch3 "C0603C104J3RACTU" 0603L 4781,3586.84 r180 bottom value=0.1uF (schematic designator C14)
C14_Ch4 "C0603C104J3RACTU" 0603L 6343,3586.76 r180 bottom value=0.1uF (schematic designator C14)
C14_Ch5 "C0603C104J3RACTU" 0603L 8298.7,3586.69 r180 bottom value=0.1uF (schematic designator C14)
C14_Ch6 "C0603C104J3RACTU" 0603L 9860.7,3586.61 r180 bottom value=0.1uF (schematic designator C14)
C14_Ch7 "C0603C104J3RACTU" 0603L 11422.7,3586.53 r180 bottom value=0.1uF (schematic designator C14)
C14_Ch8 "C0603C104J3RACTU" 0603L 12984.7,3586.45 r180 bottom value=0.1uF (schematic designator C14)
C15_Ch1 "GRM1885C1H101JA01D" 0603L 2710,2440 r180 bottom value=100pF (schematic designator C15)
C15_Ch2 "GRM1885C1H101JA01D" 0603L 4272,2439.92 r180 bottom value=100pF (schematic designator C15)
C15_Ch3 "GRM1885C1H101JA01D" 0603L 5834,2439.84 r180 bottom value=100pF (schematic designator C15)
C15_Ch4 "GRM1885C1H101JA01D" 0603L 7396,2439.76 r180 bottom value=100pF (schematic designator C15)
C15_Ch5 "GRM1885C1H101JA01D" 0603L 9351.7,2439.69 r180 bottom value=100pF (schematic designator C15)
C15_Ch6 "GRM1885C1H101JA01D" 0603L 10913.7,2439.61 r180 bottom value=100pF (schematic designator C15)
C15_Ch7 "GRM1885C1H101JA01D" 0603L 12475.7,2439.53 r180 bottom value=100pF (schematic designator C15)
C15_Ch8 "GRM1885C1H101JA01D" 0603L 14037.7,2439.45 r180 bottom value=100pF (schematic designator C15)
C16_Ch1 "GCM155R71E103KA37D" 0402 2366,5442.56 r180 top value=0.01uF (schematic designator C16)
C16_Ch2 "GCM155R71E103KA37D" 0402 3928,5442.48 r180 top value=0.01uF (schematic designator C16)
C16_Ch3 "GCM155R71E103KA37D" 0402 5490,5442.4 r180 top value=0.01uF (schematic designator C16)
C16_Ch4 "GCM155R71E103KA37D" 0402 7052,5442.32 r180 top value=0.01uF (schematic designator C16)
C16_Ch5 "GCM155R71E103KA37D" 0402 9007.7,5442.24 r180 top value=0.01uF (schematic designator C16)
C16_Ch6 "GCM155R71E103KA37D" 0402 10569.7,5442.16 r180 top value=0.01uF (schematic designator C16)
C16_Ch7 "GCM155R71E103KA37D" 0402 12131.7,5442.09 r180 top value=0.01uF (schematic designator C16)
